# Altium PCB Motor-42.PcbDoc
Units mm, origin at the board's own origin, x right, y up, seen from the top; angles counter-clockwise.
Board outline 41.2 x 41.2 mm, 4 copper layers (Top1, Signal2, Gnd3, Bottom4), stack 0.778 mm thick; 81 components, 66 nets, 267 pads, 151 vias.
Unrouted connection lines stored in the file: 54.
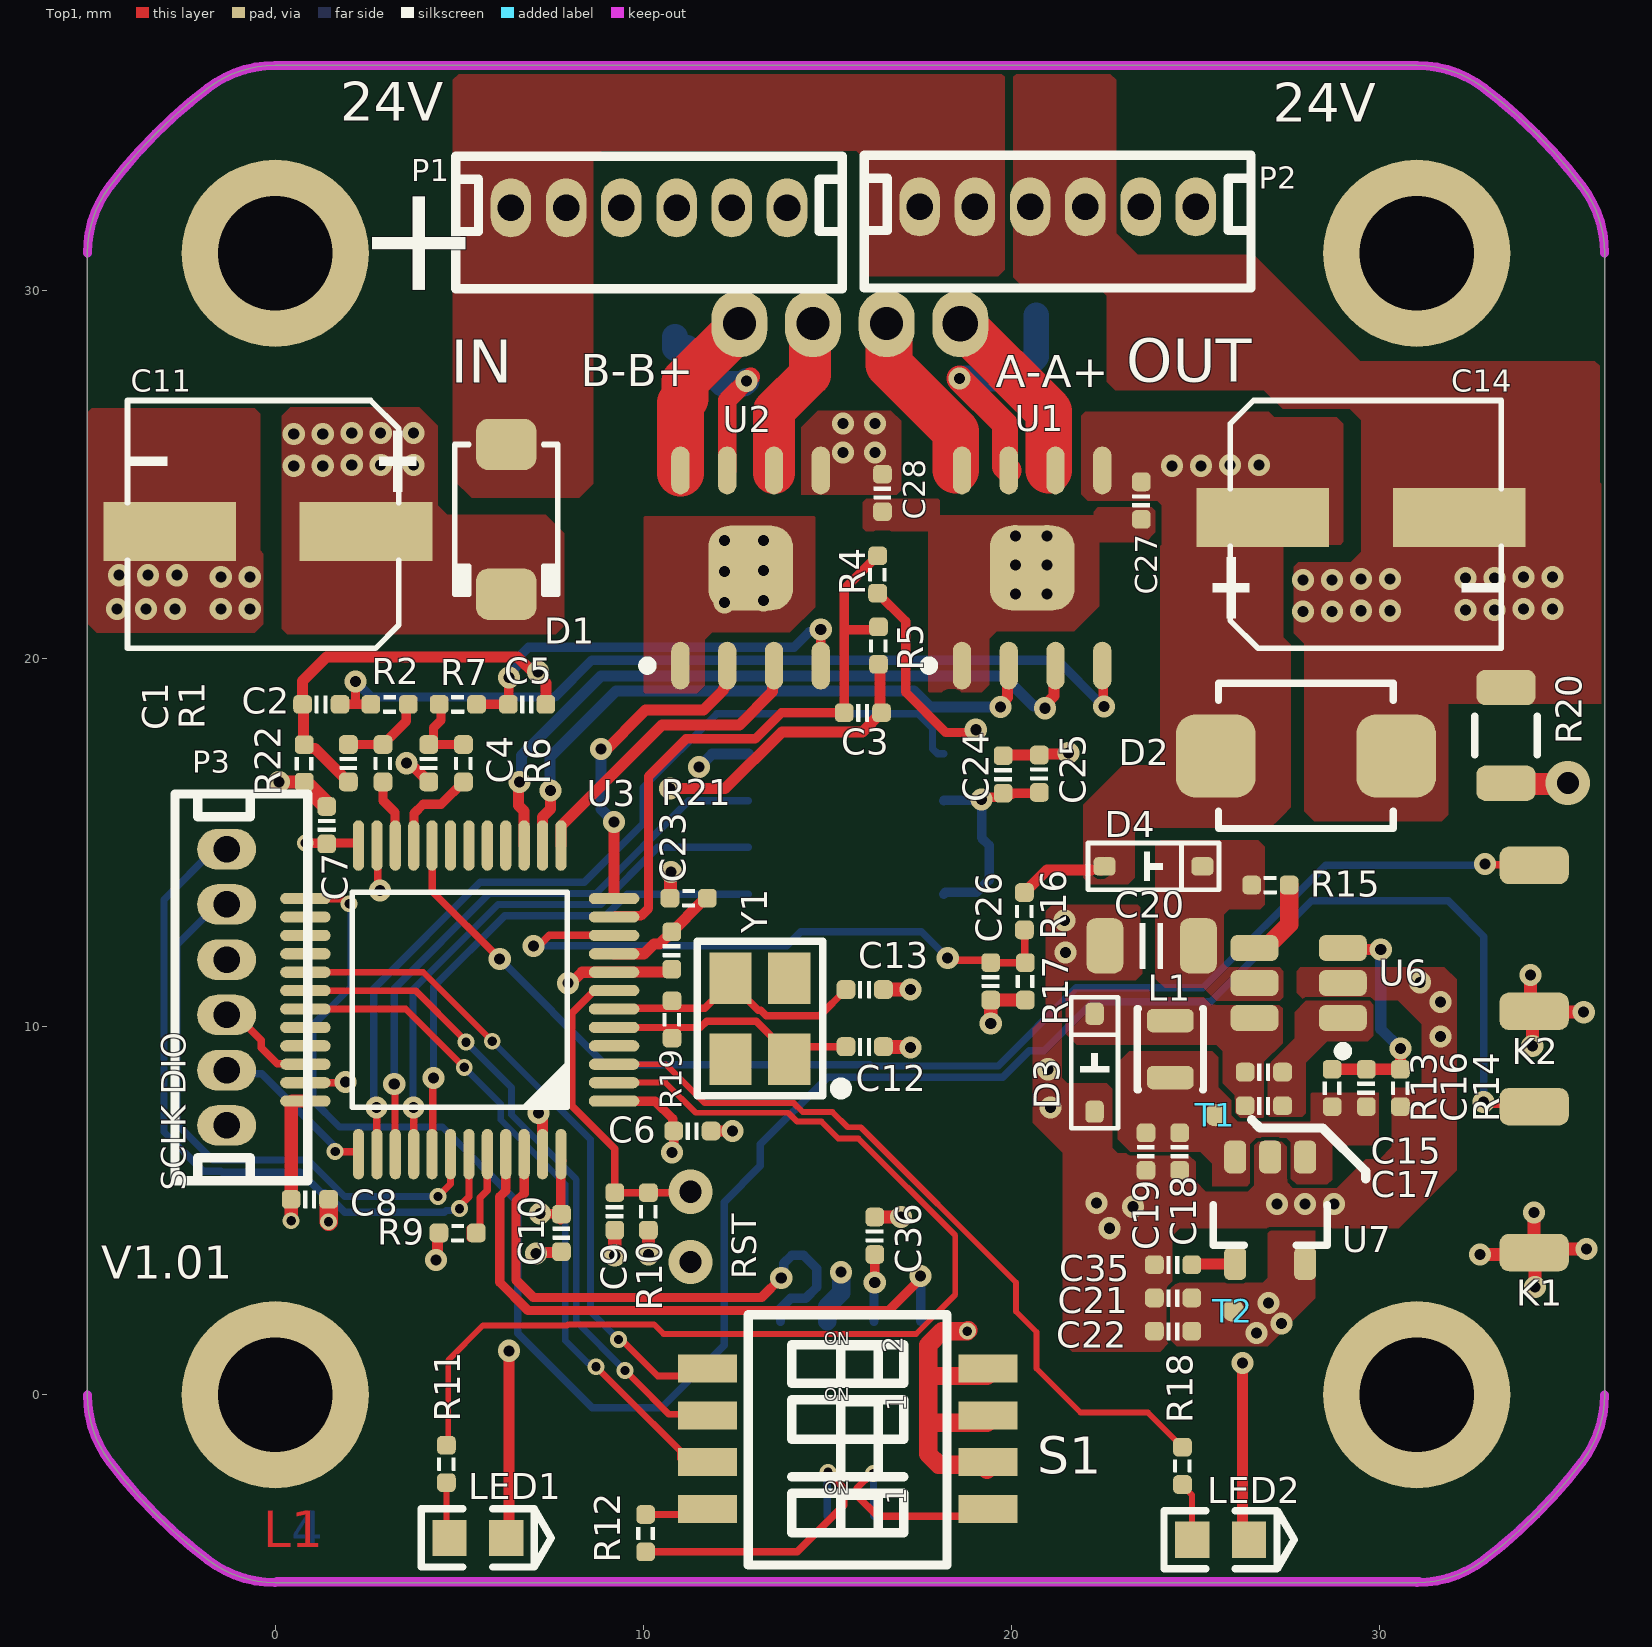
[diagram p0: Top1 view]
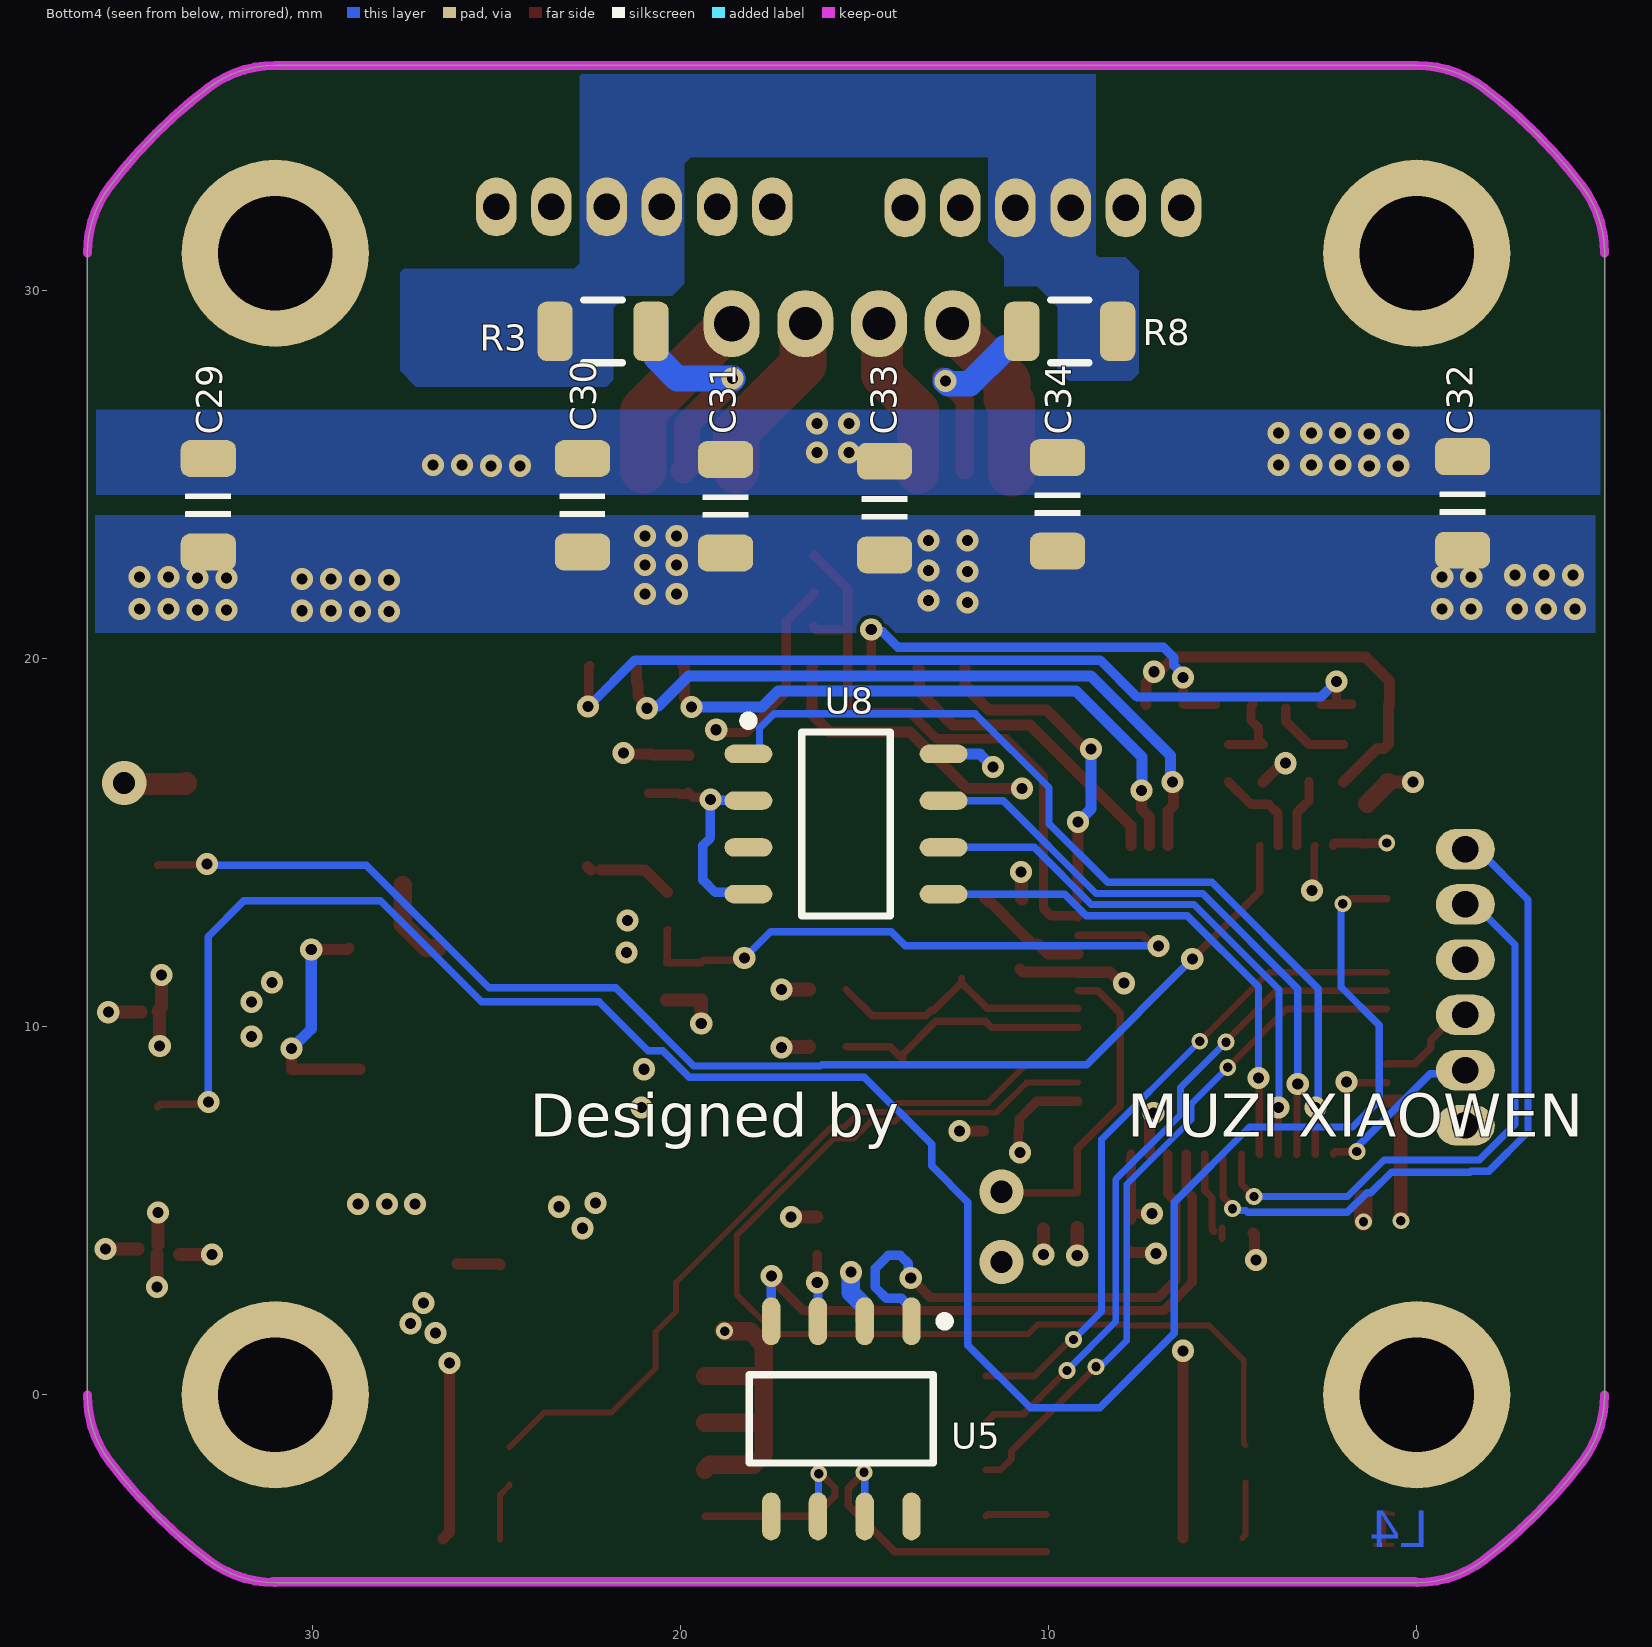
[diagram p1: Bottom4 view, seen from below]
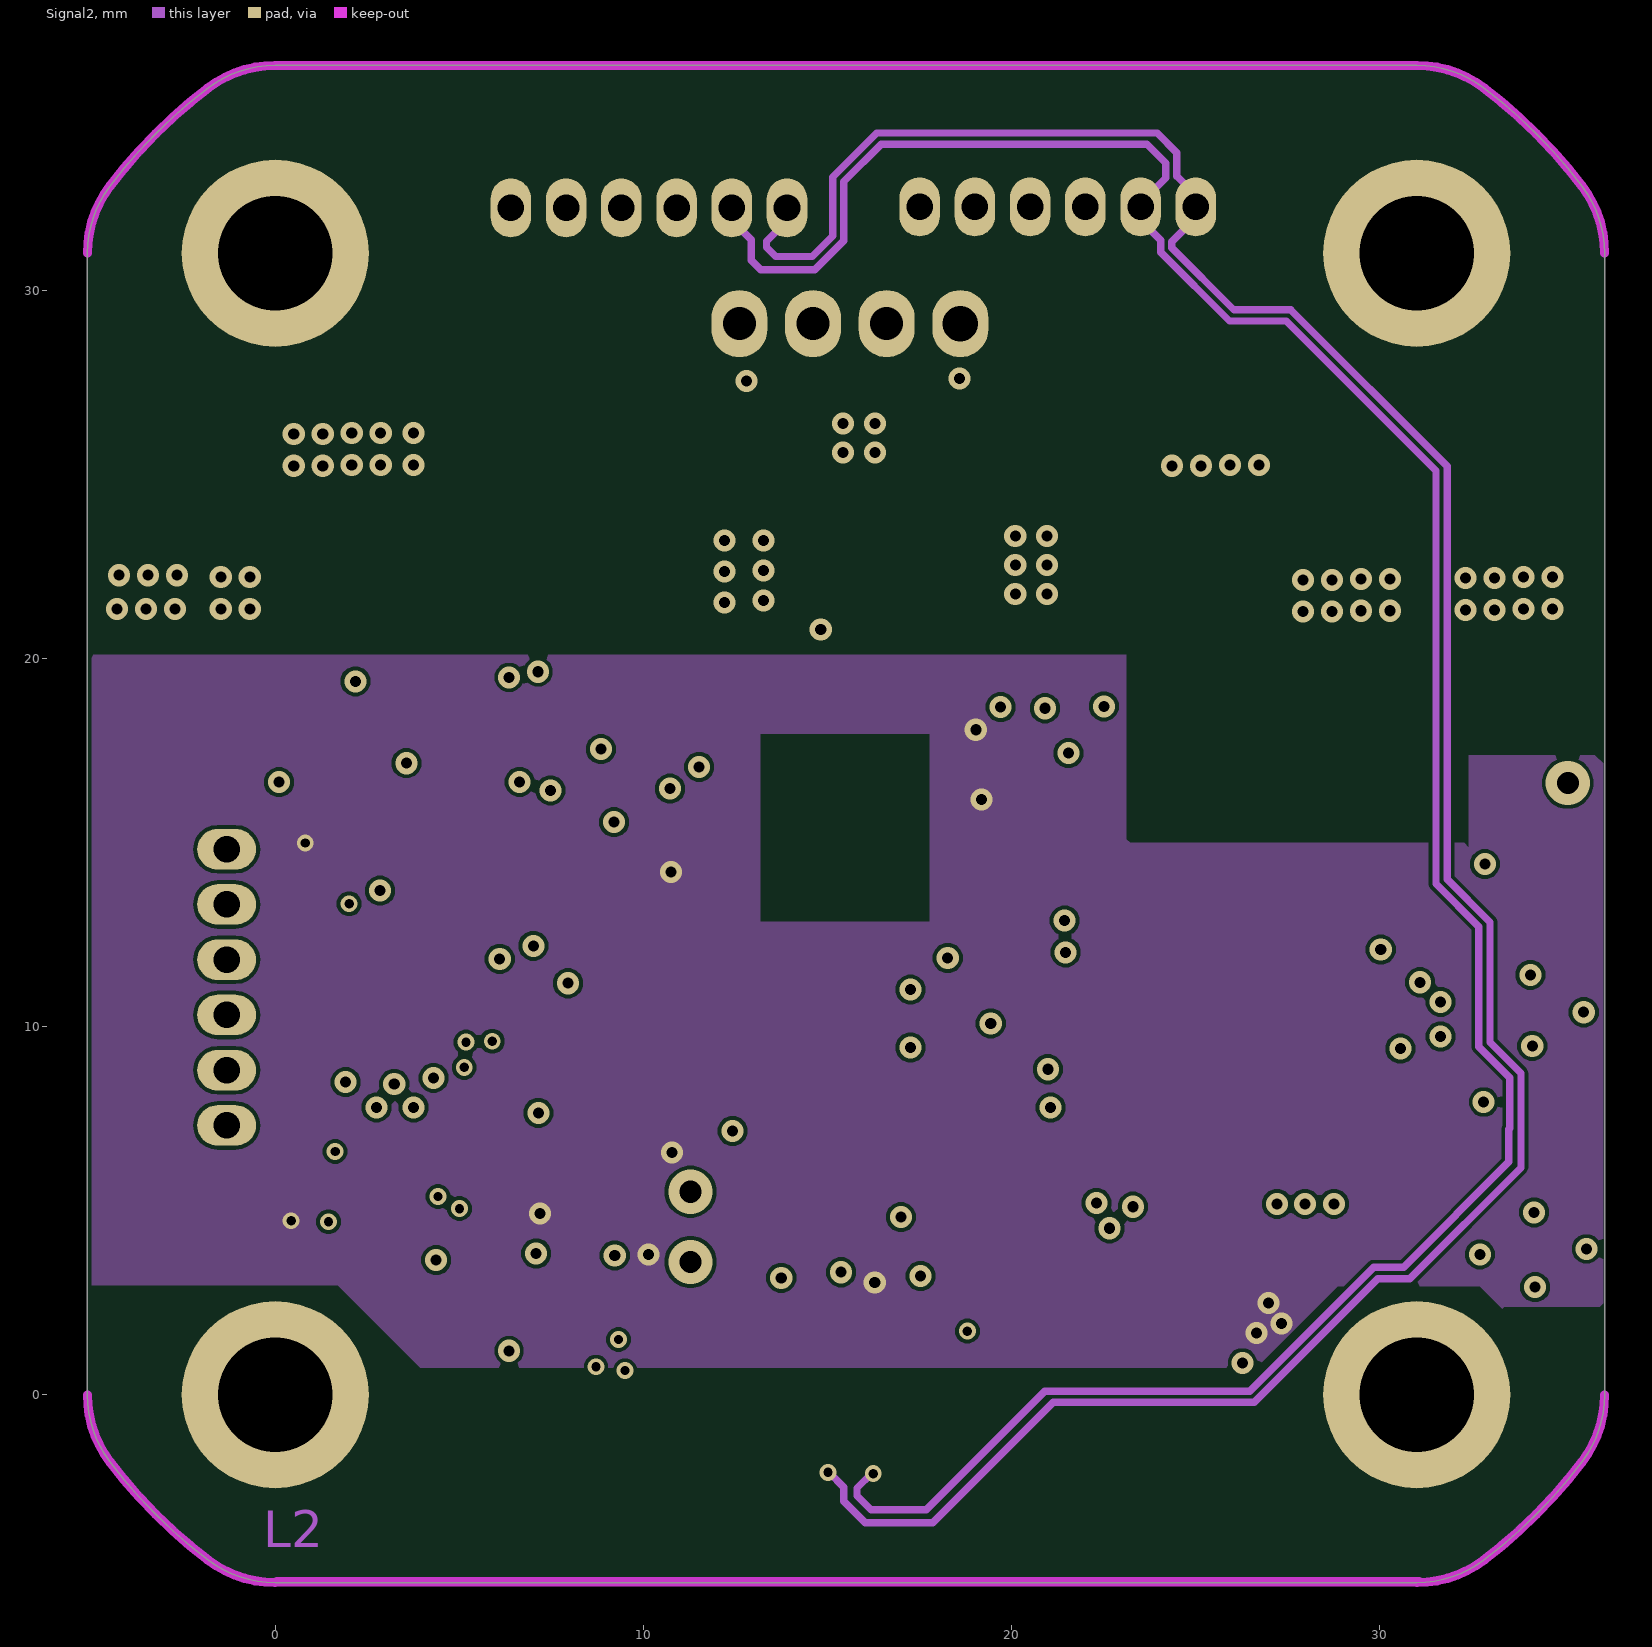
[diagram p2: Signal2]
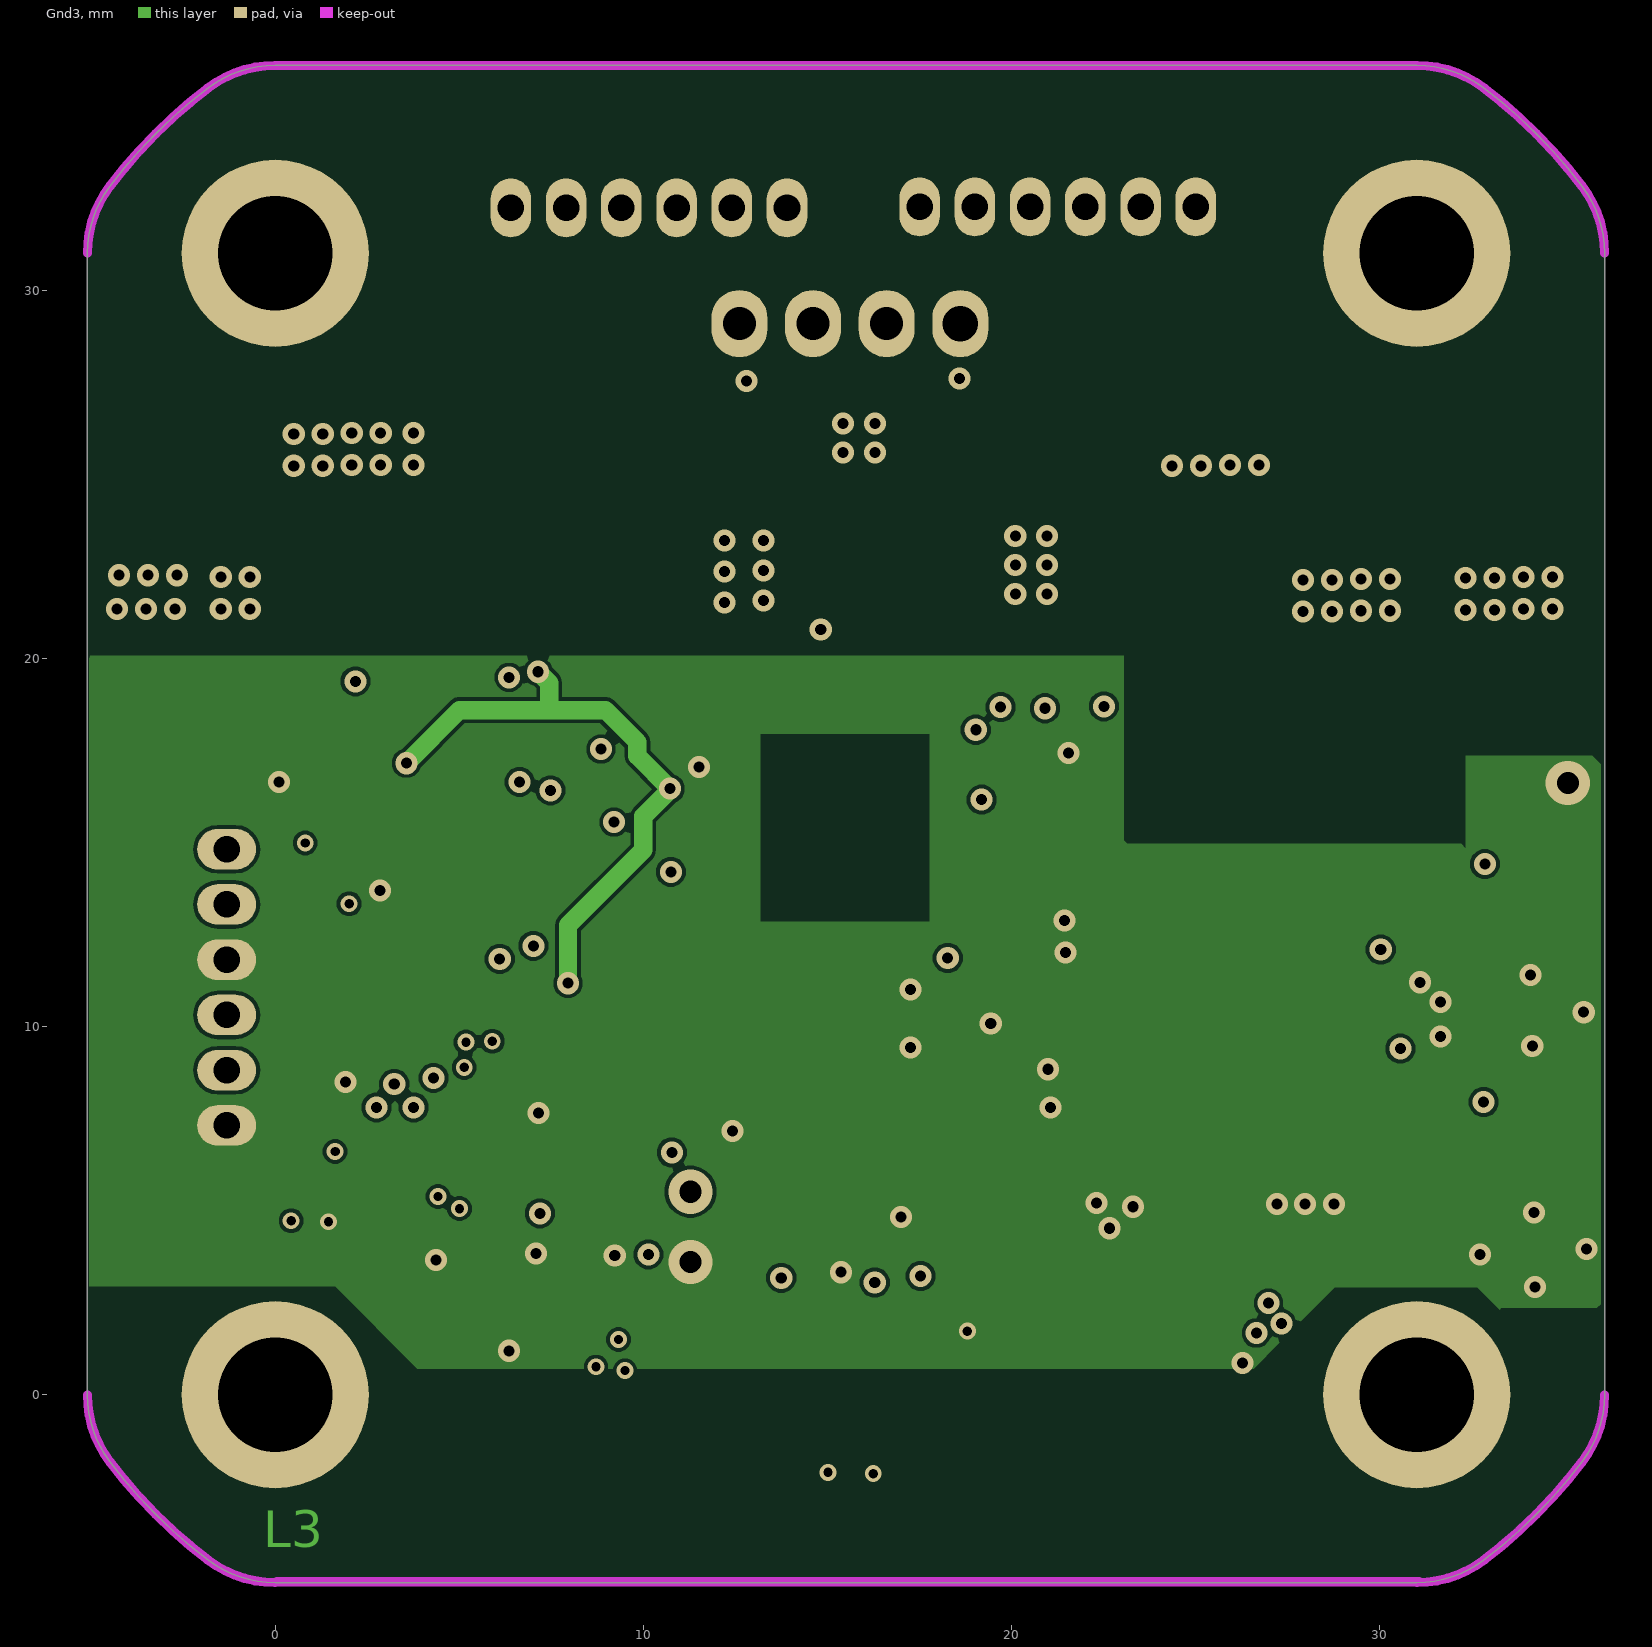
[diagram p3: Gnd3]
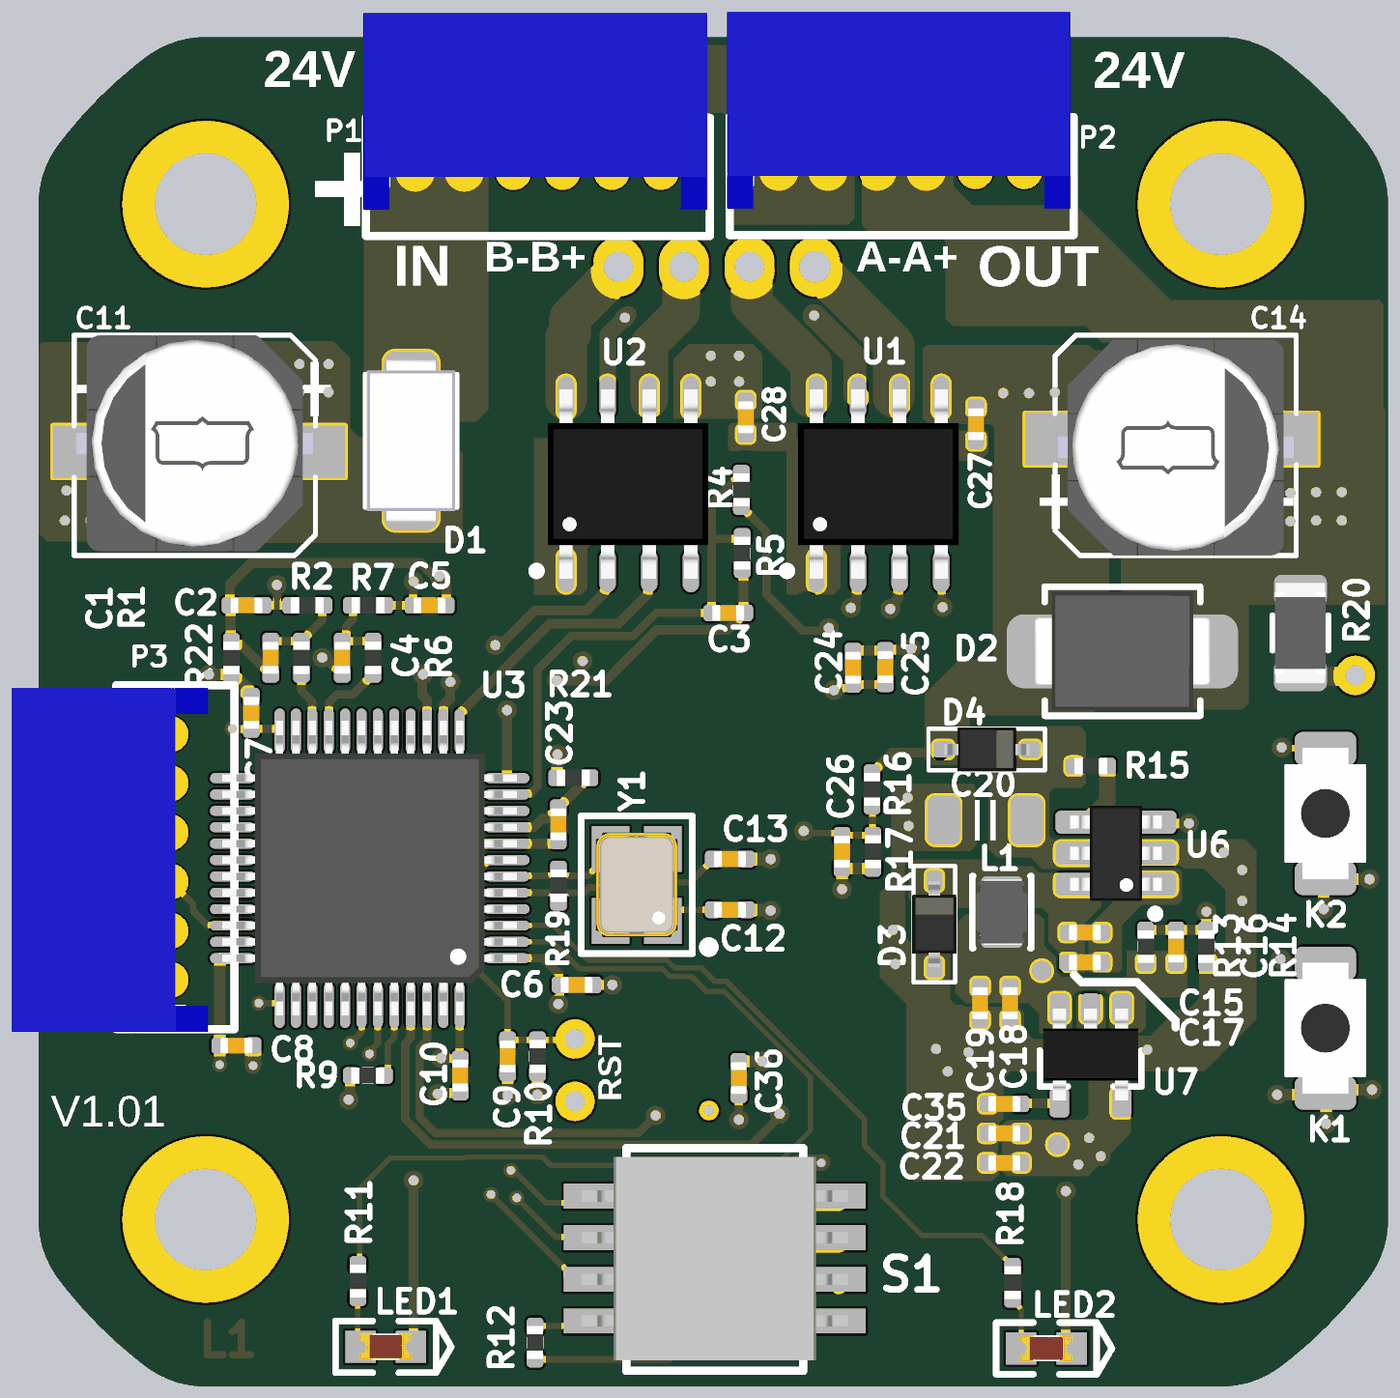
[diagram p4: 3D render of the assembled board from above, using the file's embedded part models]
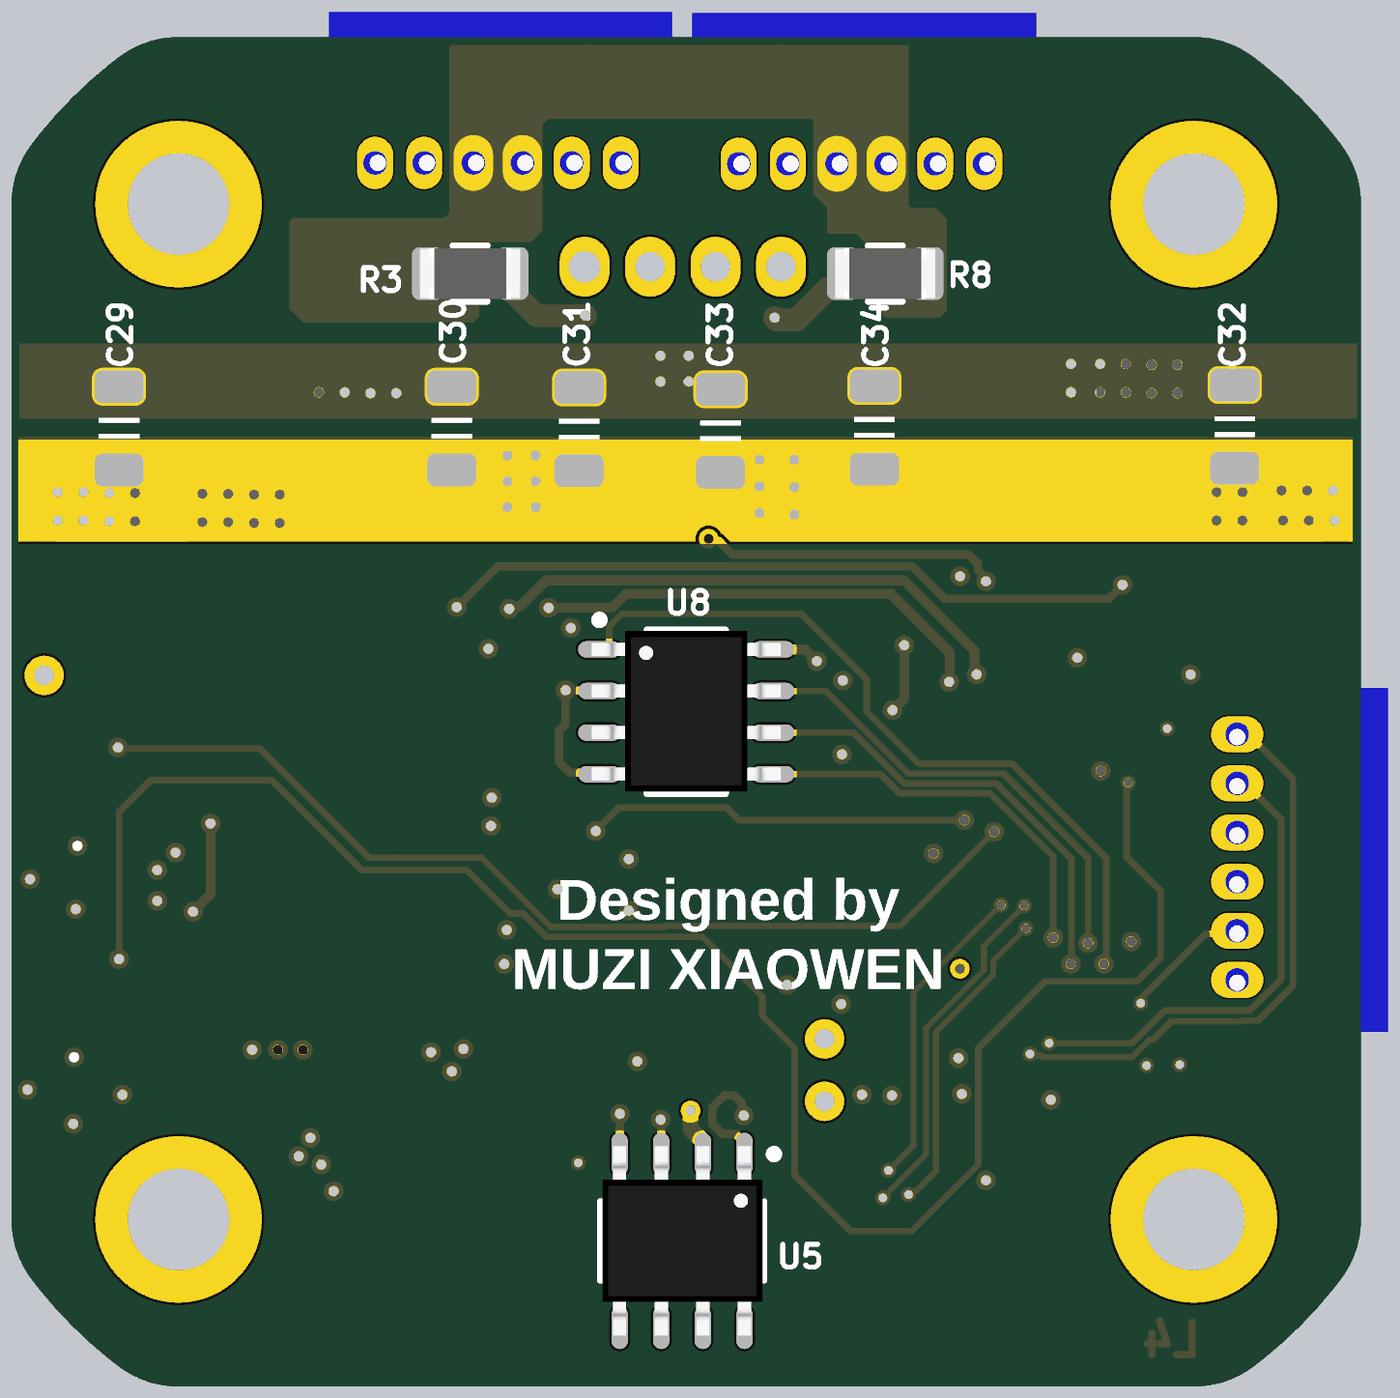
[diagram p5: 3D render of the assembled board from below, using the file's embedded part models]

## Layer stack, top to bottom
Top Solder: solder mask 0.0102, Solder Resist, Dk 3.5
Top1: signal copper 0.0356
Dielectric1: core 0.254, FR-4, Dk 4.2
Signal2: signal copper 0.036
Dielectric2: core 0.254, Dk 4.2
Gnd3: signal copper 0.036
Dielectric3: prepreg 0.127, Dk 4.2
Bottom4: signal copper 0.0356
Bottom Solder: solder mask 0.0102, Solder Resist, Dk 3.5

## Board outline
-4.493,-1.816 cw(c-2.1,-0.006) -5.1,-0.006 -5.1,23 -5.1,31.006 cw(c-2.1,31.006) -4.493,32.816 cw(c6.5,24.5) -1.816,35.493 cw(c-0.006,33.1) -0.006,36.1 31.006,36.1 cw(c31.006,33.1) 32.816,35.493 cw(c24.5,24.5) 35.493,32.816 cw(c33.1,31.006) 36.1,31.006 36.1,-0.006 cw(c33.1,-0.006) 35.493,-1.816 cw(c24.5,6.5) 32.816,-4.493 cw(c31.006,-2.1) 31.006,-5.1 -0.006,-5.1 cw(c-0.006,-2.1) -1.816,-4.493 cw(c6.5,6.5)

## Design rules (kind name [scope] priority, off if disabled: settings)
Clearance [All] p1: gap=0.102 ignorepadtopadclearanceinfootprint=FALSE except(0: Arc-Hole Track-Hole SMDPad-Hole THPad-Hole Via-Hole Fill-Hole Poly-Hole Region-Hole Text-Hole)
ComponentClearance [All] p1: gap=0 collisioncheckmode=3 verticalgap=0 showdistances=FALSE
DiffPairsRouting [All] p1: maxlimit=0.229 minlimit=0.229 mostfreqgap=0.229 toplayer_minwidth=0.381 toplayer_maxwidth=0.381 toplayer_prefwidth=0.381 midlayer1_minwidth=0.381 midlayer1_maxwidth=0.381 midlayer1_prefwidth=0.381 midlayer2_minwidth=0.381 midlayer2_maxwidth=0.381 midlayer2_prefwidth=0.381 bottomlayer_minwidth=0.381 bottomlayer_maxwidth=0.381 bottomlayer_prefwidth=0.381 maxuncoupledlength=12.7
FanoutControl Fanout_BGA [All] p1: bgadir=Out bgaviamode=Centered fanoutstyle=Auto fanoutdirection=Alternating viagrid=0.025 // Fanout_BGA (Default Rule)
HoleSize [All] p1: absolutevalues=TRUE maxlimit=254 minlimit=0.203 maxpercent=80.000 minpercent=20.000
MinimumSolderMaskSliver [All] p1 off: minsoldermaskwidth=0.051
PlaneClearance [All] p1: clearance=0.203
PlaneConnect [All] p1: planeconnectstyle=Direct reliefexpansion=0.508 reliefentries=4 reliefconductorwidth=0.254 reliefairgap=0.254
PolygonConnect [All] p1: connectstyle=Direct reliefconductorwidth=0.254 reliefentries=4 polygonreliefangle="90 Angle" airgapwidth=0.254
RoomDefinition Port [InComponentClass('Port')] p1 off: confinementstyle=ConfineIn formatcopy=TRUE lockcomponents=FALSE outline -13.335,-36.017 37.465,-36.017 37.465,-10.617 -13.335,-10.617
RoomDefinition MCU [InComponentClass('MCU')] p2 off: confinementstyle=ConfineIn formatcopy=TRUE lockcomponents=FALSE outline -13.233,-36.17 37.567,-36.17 37.567,-10.77 -13.233,-10.77
RoomDefinition Interface [InComponentClass('Interface')] p3 off: confinementstyle=ConfineIn formatcopy=TRUE lockcomponents=FALSE outline -14.453,-36.5 36.347,-36.5 36.347,-11.1 -14.453,-11.1
RoomDefinition Drive [InComponentClass('Drive')] p4 off: confinementstyle=ConfineIn formatcopy=TRUE lockcomponents=FALSE outline -13.005,-36.5 37.795,-36.5 37.795,-11.1 -13.005,-11.1
RoomDefinition Power [InComponentClass('Power')] p5 off: confinementstyle=ConfineIn formatcopy=TRUE lockcomponents=FALSE outline -12.675,-36.144 38.125,-36.144 38.125,-10.744 -12.675,-10.744
RoutingVias [All] p1: holewidth=0.203 width=0.406 viastyle="Through Hole" minholewidth=0.152 minwidth=0.305 maxholewidth=0.711 maxwidth=1.27
SilkToSilkClearance [All] p1: silktosilkclearance=0
SilkToSolderMaskClearance [IsPad] p1: minsilkscreentomaskgap=0 clearancetoexposedcopper=TRUE
SolderMaskExpansion [All] p1: expansion=0.076 istentingtop=FALSE
Width GND [(InNet('AGND') OR InNet('GND'))] p1: maxlimit=1.27 minlimit=0.102 preferedwidth=0.254
Width VCC [(InNet('VDD_SYS_3.3V') OR InNet('VDD_AV_3.3V') OR InNet('VDD_5V') OR InNet('VDD1V2-SYS') OR InNet('VDD1V1-EPHY') OR InNet('VDD-CPUX') OR InNet('VDD-CPUS') OR InNet('VDD-CPUFB') OR InNet('VCC-DRAM'))] p2: maxlimit=1.27 minlimit=0.102 preferedwidth=0.254
Width [All] p3: maxlimit=254 minlimit=0.102 preferedwidth=0.102
21 further rules are at their usual default settings.

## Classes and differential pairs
component class Port: C36 K1 K2 P1 P2 P3 R12 S1 U5
component class MCU: C6 C7 C8 C9 C10 C12 C13 C23 LED1 LED2 R9 R10 R11 R18 R19 R21 R22 U3 Y1
component class Interface: C24 C25 C26 R16 R17 U8
component class Drive: C1 C2 C3 C4 C5 C27 C28 R1 R2 R3 R4 R5 R6 R7 R8 R20 U1 U2
component class Power: C11 C14 C15 C16 C17 C18 C19 C20 C21 C22 C29 C30 C31 C32 C33 C34 C35 D1 D2 D3 D4 L1 R13 R14 R15 T1 T2 U6 U7

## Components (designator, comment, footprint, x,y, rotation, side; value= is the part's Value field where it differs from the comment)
C1 "0.1uF" CAP_0402 1.987,17.151 r90 top value=0.1u
C2 "0.1uF" CAP_0402 1.251,18.751 r0 top value=0.1u
C3 "10uF" CAP_0402 15.957,18.523 r180 top value=0.1u
C4 "0.1uF" CAP_0402 4.172,17.151 r90 top value=0.1u
C5 "0.1uF" CAP_0402 6.839,18.751 r180 top value=0.1u
C6 "0.1uF" CAP_0402 11.328,7.163 r180 top value=0.1u
C7 "0.1uF" CAP_0402 1.397,15.469 r270 top value=0.1u
C8 "0.1uF" CAP_0402 0.94,5.309 r180 top value=0.1u
C9 "0.1uF" CAP_0402 9.22,4.978 r90 top value=0.1u
C10 "10uF" CAP_0402 7.772,4.394 r90 top value=0.1u
C11 "220uF/25V" CAP-SMD_BD8.0-L8.3-W8.3-LS9.3-FD -0.076,23.444 r180 top value=150uF/35V
C12 "20pF" CAP_0402 16.008,9.455 r0 top
C13 "20pF" CAP_0402 16.008,11.004 r0 top
C14 "220uF/25V" CAP-SMD_BD8.0-L8.3-W8.3-LS9.3-FD 29.362,23.825 r0 top value=150uF/35V
C15 "0.1uF" CAP_0402 26.848,8.763 r0 top value=0.1u
C16 "100pF" CAP_0402 29.629,8.331 r90 top value=0.1u
C17 "0.1uF" CAP_0402 26.848,7.849 r0 top value=0.1u
C18 "0.1uF" CAP_0402 24.562,6.604 r90 top value=0.1u
C19 "10uF" CAP_0402 23.647,6.604 r90 top value=0.1u
C20 "10uF/50V" 1206-CAP 23.8,12.192 r0 top value=0.1u
C21 "0.1uF" CAP_0402 24.384,2.629 r0 top value=0.1u
C22 "10uF" CAP_0402 24.384,1.727 r0 top value=0.1u
C23 "0.1uF" CAP_0402 10.77,12.065 r90 top value=0.1u
C24 "10uF" CAP_0402 19.767,16.846 r270 top value=0.1u
C25 "0.1uF" CAP_0402 20.752,16.866 r270 top value=0.1u
C26 "0.1uF" CAP_0402 19.431,11.227 r90 top value=0.1u
C27 "0.1uF" CAP_0402 23.52,24.282 r90 top value=0.1u
C28 "0.1uF" CAP_0402 16.491,24.492 r90 top value=0.1u
C29 "10uF/50V" 1206-CAP 32.817,24.155 r270 bottom
C30 "10uF/50V" 1206-CAP 22.657,24.155 r270 bottom
C31 "10uF/50V" 1206-CAP 18.771,24.13 r270 bottom
C32 "10uF/50V" 1206-CAP -1.245,24.206 r270 bottom
C33 "10uF/50V" 1206-CAP 14.453,24.079 r270 bottom
C34 "10uF/50V" 1206-CAP 9.754,24.181 r270 bottom
C35 "0.1uF" CAP_0402 24.384,3.531 r0 top value=0.1u
C36 "0.1uF" CAP_0402 16.281,4.318 r270 top value=0.1u
D1 "SS54" DO-214AC 6.274,23.774 r270 top
D2 "SMBJ28CA" SMBJ-CA_MFG 27.991,17.348 r180 top
D3 "二极管-5819W" SOD-323 22.25,9.017 r90 top
D4 "二极管-5819W" SOD-323 23.851,14.351 r0 top
K1 "TACT 2P" ButtonTACT_3x4x2_180 34.188,5.842 r90 top value=3x4
K2 "TACT 2P" ButtonTACT_3x4x2_180 34.188,12.395 r90 top value=3x4
L1 "6.8uH" IND-201612 24.308,9.384 r270 top
LED1 "LED GREEN" LED-0603 5.512,-3.937 r180 top
LED2 "LED GREEN" LED-0603 25.683,-3.985 r180 top
P1 "Header 6H" CONN-TH_HC-ZH1.5-6A-s 10.148,32.233 r0 top
P2 "Header 6H" CONN-TH_HC-ZH1.5-6A-s 21.249,32.258 r0 top
P3 "Header 6H" CONN-TH_HC-ZH1.5-6A-s -1.321,11.064 r90 top locked
R1 "1K" RES_0402 2.927,17.151 r90 top value=22R
R2 "1K" RES_0402 3.105,18.751 r180 top value=22R
R3 "0.1R" 1206-RES 22.098,28.88 r0 bottom value=22R
R4 "NCP15XH103F03RC" RES_0402 16.358,22.276 r270 top value=10k
R5 "3.3K" RES_0402 16.383,20.345 r90 top value=22R
R6 "1K" RES_0402 5.111,17.151 r90 top value=22R
R7 "1K" RES_0402 4.959,18.751 r0 top value=22R
R8 "0.1R" 1206-RES 9.423,28.88 r180 bottom value=22R
R9 "10K" RES_0402 4.953,4.394 r180 top value=22R
R10 "10K" RES_0402 10.135,4.978 r270 top value=22R
R11 "1K" RES_0402 4.648,-1.88 r270 top value=22R
R12 "120R" RES_0402 10.058,-3.759 r90 top value=22R
R13 "10K" RES_0402 28.702,8.331 r270 top value=22R
R14 "1.8K" RES_0402 30.556,8.331 r90 top value=22R
R15 "1M" RES_0402 27.026,13.843 r0 top value=22R
R16 "10K" RES_0402 20.345,13.132 r270 top value=22R
R17 "1K" RES_0402 20.371,11.227 r270 top value=22R
R18 "1K" RES_0402 24.638,-1.93 r270 top value=22R
R19 "1M" RES_0402 10.776,10.191 r270 top value=22R
R20 "0R" 1206-RES 33.426,17.907 r90 top
R21 "0" RES_0402 11.227,13.487 r180 top value=0R
R22 "0" RES_0402 0.787,17.145 r90 top value=0R
S1 "DSHP04TSGER" SW-SMD_DSHP04TS-S 11.735,-0.559 r90 top
T1 "测试点" TEST_PT 25.527,7.594 r0 top
T2 "测试点" TEST_PT 26.01,2.286 r90 top
U1 "TB67H450FNG" SO-8-PAD 20.555,22.451 r0 top locked
U2 "TB67H450FNG" SO-8-PAD 12.909,22.451 r0 top locked
U3 "STM32F103CBT6" LQFP-48 5.01,10.725 r0 top locked
U5 "SN65HVD232D" so-8 15.627,-0.654 r90 bottom locked
U6 "ME3116" SOT23-6 27.794,11.182 r90 top
U7 "LP2992 3V3" SOT23-5 27.02,4.958 r180 top
U8 "MT6816" SO-8 15.5,15.5 r180 bottom locked
Y1 "XTAL-4" LC-SMD-3225_4P 13.163,10.217 r90 top value="12 MHz"

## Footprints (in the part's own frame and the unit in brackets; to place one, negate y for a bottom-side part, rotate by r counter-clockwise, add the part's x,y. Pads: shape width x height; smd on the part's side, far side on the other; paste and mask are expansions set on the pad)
1206-CAP [mm]
  rrect50% 1x1.5 smd: 1(-1.27,0) 2(1.27,0)
  silkscreen extent -0.3,-0.61 0.3,0.61, body extent -1.5,-0.75 1.5,0.75, height 1.5
1206-RES [mm]
  rrect50% 0.956x1.61 smd paste+0 mask+0: 1(-1.301,0) 2(1.301,0)
  silkscreen extent -0.52,-0.85 0.52,0.85, body extent -1.55,-0.77 1.55,0.77, height 0.65
ButtonTACT_3x4x2_180 [mil]
  rrect50% 40x74 smd: 1(-78,0) 2(78,0)
  body extent -79,-49 79,49, height 63
CAP-SMD_BD8.0-L8.3-W8.3-LS9.3-FD [mm]
  rect 3.6x1.6 smd: 1(-2.54,0) 2(2.794,0)
  silkscreen extent -3.9,-3.56 3.94,3.18, body extent -3.35,-3.55 3.85,3.05, height 7.7
CAP_0402 [mil]
  rrect50% 20x20 smd: 1(-20,0) 2(20,0)
  silkscreen extent -7,-9 7,9, body extent -20,-10 20,10, height 20
CONN-TH_HC-ZH1.5-6A-s [mm]
  oval 1.1x1.6 hole 0.72 paste+0 mask+0.05: 1(-3.75,0) 2(-2.25,0) 3(-0.75,0) 4(0.75,0) 5(2.25,0) 6(3.75,0)
  silkscreen extent -5.25,-2.2 5.25,1.4, body extent -5.34,-1.4 5.16,4.6, height 4
DO-214AC [mil] "SMA"
  rrect50% 55x65 smd: 1(-80,0) 2(80,0)
  silkscreen extent -80,-55 80,55, body extent -98,-53 98,53, height 85
IND-201612 [mm]
  rrect50% 0.635x1.27 smd paste+0 mask+0: 1(-0.774,0) 2(0.774,0)
  silkscreen extent -1.1,-0.9 1.1,0.9, body extent -1,-0.8 1,0.8, height 0.95
LC-SMD-3225_4P [mm]
  rect 1.4x1.15 smd: 1(-1.1,-0.8) 2(1.1,-0.8) 3(1.1,0.8) 4(-1.1,0.8)
  silkscreen extent -2.1,-2.35 2.1,1.7, body extent -1.6,-1.25 1.6,1.25, height 0.61
LED-0603 [mm]
  rect 0.93x0.98 smd: A(0.782,-0.048) C(-0.758,-0.048)
  silkscreen extent -1.99,-0.84 1.55,0.74, body extent -0.79,-0.45 0.81,0.35, height 0.6
LQFP-48 [mil]
  oval 54x12 smd: 1(165,-108.27) 2(165,-88.58) 3(165,-68.9) 4(165,-49.21) 5(165,-29.53) 6(165,-9.84) 7(165,9.84) 8(165,29.53) 9(165,49.21) 10(165,68.9) 11(165,88.58) 12(165,108.27) 25(-165,108.27) 26(-165,88.58) 27(-165,68.9) 28(-165,49.21) 29(-165,29.53) 30(-165,9.84) 31(-165,-9.84) 32(-165,-29.53) 33(-165,-49.21) 34(-165,-68.9) 35(-165,-88.58) 36(-165,-108.27)
  oval 12x54 smd: 13(108.27,165) 14(88.58,165) 15(68.9,165) 16(49.21,165) 17(29.53,165) 18(9.84,165) 19(-9.84,165) 20(-29.53,165) 21(-49.21,165) 22(-68.9,165) 23(-88.58,165) 24(-108.27,165) 37(-108.27,-165) 38(-88.58,-165) 39(-68.9,-165) 40(-49.21,-165) 41(-29.53,-165) 42(-9.84,-165) 43(9.84,-165) 44(29.53,-165) 45(49.21,-165) 46(68.9,-165) 47(88.58,-165) 48(108.27,-165)
  silkscreen extent -115,-115 115,115, body extent -177,-177 177,177, height 61
RES_0402 [mil]
  rrect50% 20x20 smd: 1(-20,0) 2(20,0)
  silkscreen extent -7,-10 7,10, body extent -20,-10 20,10, height 14
SMBJ-CA_MFG [mm]
  rrect50% 2.16x2.26 smd paste+0 mask+0: 1(-2.45,0) 2(2.45,0)
  silkscreen extent -2.37,-1.97 2.37,1.97, body extent -2.7,-1.81 2.7,1.81, height 2.62
so-8 [mm]
  oval 1.3x0.5 smd: 1(2.65,-1.905) 2(2.65,-0.635) 3(2.65,0.635) 4(2.65,1.905) 5(-2.65,1.905) 6(-2.65,0.635) 7(-2.65,-0.635) 8(-2.65,-1.905)
  silkscreen extent -1.2,-2.93 2.77,2.5, body extent -2.89,-2.46 2.89,2.44, height 1.45
SO-8 [mm]
  oval 1.3x0.5 smd: 1(-2.65,1.905) 2(-2.65,0.635) 3(-2.65,-0.635) 4(-2.65,-1.905) 5(2.65,-1.905) 6(2.65,-0.635) 7(2.65,0.635) 8(2.65,1.905)
  silkscreen extent -2.78,-2.5 1.2,2.93, body extent -2.89,-2.44 2.89,2.46, height 1.45
SO-8-PAD [mm]
  oval 0.5x1.3 smd: 1(-1.905,-2.65) 2(-0.635,-2.65) 3(0.635,-2.65) 4(1.905,-2.65) 5(1.905,2.65) 6(0.635,2.65) 7(-0.635,2.65) 8(-1.905,2.65)
  rrect50% 2.3x2.3 smd: 9(0,0)
  silkscreen extent -2.93,-2.77 -2.68,-2.53, body extent -2.46,-2.89 2.44,2.89, height 1.45
SOD-323 [mm]
  rrect50% 0.6x0.5 smd: 1(-1.329,0) 2(1.329,0)
  silkscreen extent -1.78,-0.64 1.78,0.64, body extent -1.3,-0.68 1.3,0.67, height 1.15
SOT23-5 [mm] "SOT23, 3-Leads, Body 3.1x3.0mm (max), Pitch 0.95mm, IPC Medium Density"
  rrect50% 0.6x0.889 smd: 1(-0.95,-1.5) 2(0,-1.5) 3(0.95,-1.5) 4(0.95,1.396) 5(-0.95,1.396)
  silkscreen extent -1.55,-0.2 1.55,0.9, body extent -1.45,-1.48 1.45,1.32, height 1.2
SOT23-6 [mm]
  rrect50% 0.7x1.3 smd: 1(-0.95,-1.2) 2(0,-1.2) 3(0.95,-1.2) 4(0.95,1.2) 5(0,1.2) 6(-0.95,1.2)
  silkscreen extent -1.97,-1.33 -1.73,-1.08, body extent -1.45,-1.4 1.45,1.4, height 1.45
SW-SMD_DSHP04TS-S [mm]
  rect 0.762x1.6 smd: 1(1.27,0) 2(0,0) 3(-1.27,0) 4(-2.54,0) 5(-2.54,-7.62) 6(-1.27,-7.62) 7(0,-7.62) 8(1.27,-7.62)
  silkscreen extent -4.06,-6.51 2.73,-1.11, body extent -3.73,-7.87 2.46,0.25, height 1.71
TEST_PT [mm]
  rrect100% 0.606x0.606 smd: 0(0,0)

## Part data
C1 C2 C3 C4 C5 C6 C7 C8 C9 C10 C12 C13 C15 C16 C17 C18 C19 C20 C21 C22 C23 C24 C25 C26 C27 C28 C35 C36: library part 电容-0402, "Capacitor"
C11 C14 C29 C30 C31 C32 C33 C34: library part CAP, "Capacitor, chip, ceramic"
D1: library part Diode_SMA, "Diode"
D3 D4: "40V"
K1 K2: library part ButtonTACT_3x4x2_180, "Button"
L1: library part 电感-201612
LED1 LED2: library part LED, "LED GRN SGL RA 25mA 4.1V SMD"
P1 P2 P3: "Header, 6-Pin, Right Angle"
R1 R2 R5 R6 R7 R9 R10 R11 R12 R13 R14 R15 R16 R17 R18 R19 R21 R22: library part 电阻-0402, "Resistor"
R3 R8 R20: library part 电阻-1206, "Resistor"
R4: "THERMISTOR 10K OHM NTC 0402 SMD"
S1: library part 218-4LPSTJ, "DIP Switches / SIP Switches 4 pos. low profile Btm Seal Tape J Bend", Manufacturer_Name=CTS, Mouser Part Number=774-218-4LPSTJ
U1 U2: "PWM Chopper Type DC Brushed Motor Driver"
U3: "ARM Cortex-M3 32-bit MCU, 128 KB Flash, 20 KB Internal RAM, 37 I/Os, 48-pin LQFP, -40 to 85 degC, Tray", I/Os (High Current)=37, Operating Frequency(F) (Processor speed) (MHz)=72, Supplier Part Number 1=497-6288-ND, Supply Voltage(Vcc) min (V)=2
U5: Manufacturer="Texas Instruments", Manufacturer Part Number=SN65HVD232DR, Operating Temperature="-40癈 ~ 85癈", Package / Case="8-SOIC (0.154\", 3.90mm Width)", Supplier Device Package=8-SOIC, Supplier Part Number 1=296-26344-2-ND, Voltage - Supply="3 V ~ 3.6 V"
U6: "DC-DC"
U7: library part LP2992, "LDO"
U8: "Magnetic Position Sensor"
Y1: "Crystal"

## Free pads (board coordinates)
  oval 1.524x1.824 hole 0.9: 11(12.604,29.089) 12(14.604,29.089) 13(16.604,29.089)
  oval 1.524x1.824 hole 0.962: 14(18.604,29.089)
  round 5.08 hole 3.1: ""(0,0) ""(0,31) ""(31,0) ""(31,31)

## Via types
v1: diameter 0.6, hole 0.3, Top1 to Bottom4, tented both sides, 130 vias
v2: diameter 0.457, hole 0.254, Top1 to Bottom4, tented both sides, 14 vias
v3: diameter 1.2, hole 0.6, Top1 to Bottom4, 3 vias
v4: diameter 0.457, hole 0.254, Top1 to Bottom4, 2 vias
v5: diameter 0.6, hole 0.3, Top1 to Bottom4, 2 vias

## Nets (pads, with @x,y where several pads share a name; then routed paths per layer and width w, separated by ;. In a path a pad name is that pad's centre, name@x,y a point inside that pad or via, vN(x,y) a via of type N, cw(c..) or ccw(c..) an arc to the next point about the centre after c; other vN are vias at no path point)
ADC_ENC: U3.16
AGND: C1.1 C2.1 C3.1 C4.1 C5.1 C23.1 R5.1 R22.2 U3.8 | length 39.3
  Top1 w0.3: C1.1 1.081,17.549 0.891,17.549 R22.2 0.765,17.675 0.765,18.729 C2.1 0.743,19.386 1.397,20.041 6.579,20.041 v1@7.061,19.558 ; v1(3.562,17.151) 3.619,17.094 3.721,17.094 C4.1 ; v1(7.137,19.634) 7.195,19.577 7.195,19.475 7.347,19.323 C5.1 ; v1(7.95,11.176) 8.031,11.176 8.329,11.474 9.2,11.474 U3.8 U3.8 10.688,11.476 C23.1 ; v1(10.72,16.459) 12.219,16.459 13.76,18 15.943,18 C3.1 16.424,18.564 16.424,19.796 R5.1
  Gnd3 w0.5: v1(3.562,17.151) 5.004,18.593 7.442,18.593 ; v1(7.137,19.634) 7.442,19.329 7.442,18.593 ; v1(7.95,11.176) 7.95,12.751 9.994,14.794 9.994,15.706 10.72,16.432 v1(10.72,16.459) 9.834,17.346 9.834,17.725 8.966,18.593 7.442,18.593
BUTTON_1: K1.2 U3.25 | length 59
  Top1 w0.2: U3.25 1.797,13.475 1.937,13.335 v2(2.007,13.335) ; v1(32.817,7.95) 32.88,7.887 34.125,7.887 K1.2
  Bottom4 w0.2: v2@2.057,13.335 2.057,11.074 1.016,10.033 1.016,8.001 1.747,7.27 4.541,7.27 6.585,5.226 6.585,1.668 8.609,-0.356 10.49,-0.356 12.192,1.346 12.192,5.231 13.175,6.214 13.175,6.799 15.002,8.626 19.759,8.626 20.473,9.341 20.879,9.341 22.206,10.668 25.4,10.668 28.143,13.411 31.852,13.411 32.817,12.446 v1(32.817,7.95)
BUTTON_2: K2.2 U3.20 | length 35.4
  Top1 w0.2: U3.20 4.268,14.907 4.268,13.664 v1(6.096,11.836) ; v1(32.851,14.411) 32.869,14.394 34.171,14.394 K2.2
  Bottom4 w0.2: v1(6.096,11.836) 8.966,8.966 16.153,8.966 16.192,8.928 19.634,8.928 21.755,11.049 25.197,11.049 28.524,14.376 32.817,14.376 v1(32.851,14.411)
CAN_H: P1.6 P2.6 R12.1 U5.7 | length 79.7
  Top1 w0.2: R12.1 14.173,-4.267 15.443,-2.997 15.443,-2.54 v4(15.011,-2.108)
  Signal2 w0.2: P1.6 13.898,31.881 13.342,31.325 13.342,31.159 13.589,30.912 14.585,30.912 15.142,31.469 15.142,33.073 16.334,34.265 23.952,34.265 24.486,33.731 24.486,33.096 24.999,32.583 P2.6 24.999,31.962 24.351,31.314 24.351,31.148 26.038,29.461 27.582,29.461 31.827,25.217 31.827,13.995 32.99,12.832 32.99,9.575 33.83,8.736 33.83,6.169 30.81,3.15 29.939,3.15 26.587,-0.203 21.133,-0.203 17.856,-3.48 16.027,-3.48 15.443,-2.896 15.443,-2.515 15.037,-2.108 v4(15.011,-2.108)
  Bottom4 w0.2: U5.7@14.989,-3.301 U5.7 14.992,-2.204 v4@15.011,-2.184
CAN_L: P1.5 P2.5 S1.5 U5.6 | length 76.4
  Top1 w0.2: v4(16.238,-2.141) 16.191,-2.141 15.799,-2.533 15.799,-2.743 16.358,-3.302 S1.5@19.329,-3.302
  Signal2 w0.2: P1.5 12.398,31.9 12.929,31.369 12.929,30.81 13.183,30.556 14.656,30.556 15.443,31.344 15.443,32.948 16.455,33.96 23.673,33.96 24.181,33.452 24.181,33.045 23.499,32.364 23.499,31.906 24.049,31.356 24.049,31.023 25.913,29.159 27.457,29.159 31.521,25.095 31.521,13.874 32.688,12.707 32.688,9.45 33.528,8.611 33.528,7.239 33.503,7.214 33.503,6.325 30.645,3.467 29.83,3.467 26.462,0.098 20.901,0.098 17.678,-3.124 16.18,-3.124 15.799,-2.743 15.799,-2.533 16.191,-2.141 v4(16.238,-2.141)
  Bottom4 w0.2: v4@16.231,-2.134 16.246,-2.149 16.246,-3.289 U5.6
CAN_RX: U3.45 U5.4 | length 17
  Top1 w0.254: U3.45 6.26,5.538 6.096,5.375 6.096,3.053 6.863,2.286 16.662,2.286 17.526,3.15 v1(17.526,3.226)
  Bottom4 w0.254: v1(17.526,3.226) 17.529,3.223 17.529,1.999 U5.4
CAN_TX: U3.46 U5.1 | length 14.8
  Top1 w0.254: U3.46 6.76,5.467 6.538,5.246 6.538,3.114 7.01,2.642 13.208,2.642 v1(13.741,3.175)
  Bottom4 w0.254: U5.1 13.722,2.344 13.994,2.616 14.402,2.616 14.707,2.921 14.707,3.429 14.351,3.785 14.024,3.785 13.805,3.566 13.805,3.239 v1(13.741,3.175)
GND: C6.1 C7.1 C8.1 C9.1 C10.1 C12.2 C13.2 C18.1 C19.1 C20.1 C21.1 C22.1 C24.1 C25.1 C26.1 C35.1 C36.1 D3.1 K1.1 K2.1 LED1.C LED2.C P3.1 P3.4 R9.2 R14.1 R17.2 R20.1 R22.1 S1.6 S1.7 S1.8 U3.23 U3.35 U3.47 U5.2 U6.2 U7.2 U8.8 | length 43.9
  Top1 w0.2: U3.35 v1@1.82,8.475 ; U3.23 2.78,14.896 2.78,13.756 v1(2.845,13.691)
  Top1 w0.3: v1(4.369,3.658) 4.407,3.696 4.407,4.356 R9.2 ; LED1.C@6.346,-3.889 6.35,-3.885 v1(6.35,1.194) ; v1(7.087,3.835) 7.112,3.861 7.747,3.861 C10.1 ; v5(7.145,7.653) 7.145,7.572 7.259,7.459 7.259,6.535 U3.47 ; C6.1@11.76,7.163 v1@12.243,7.163 ; C24.1 19.786,17.373 C25.1 20.777,17.399 21.514,17.399 v1(21.539,17.424) ; v1(26.264,0.864) 26.264,-3.734 LED2.C@26.441,-3.912
  Top1 w0.354: v1(0.102,16.637) R22.1 ; v1(9.22,3.785) C9.1@9.22,4.547 ; C36.1 v1@16.891,4.826 ; v1(19.431,10.084) C26.1 R17.2 ; v1(32.715,3.81) K1.1@33.604,3.81 ; v1(34.087,11.405) 34.087,10.516 K2.1 ; v1(34.138,9.474) K2.1@34.138,10.363 ; K1.1@34.188,4.064 v1(34.188,4.953) ; v1(34.214,2.921) K1.1@34.214,3.81 ; K2.1@34.646,10.389 v1(35.535,10.389) ; K1.1@34.722,3.962 v1(35.611,3.962)
  Top1 w0.39: C12.2 16.529,9.442 17.24,9.442 v1(17.253,9.429) ; C13.2 v1(17.253,11.004)
  Top1 w0.5: R22.1 0.787,16.612 C7.1@1.346,16.053 ; v2(1.448,4.699) C8.1 ; v2@18.821,1.753 v2(18.796,1.727) 18.11,1.727 17.729,1.346 17.729,0.473 ; S1.6@19.329,-2.032 19.198,-1.901 18.022,-1.901 17.729,-1.608 17.729,-0.66 ; S1.7@19.329,-0.762 17.831,-0.762 17.729,-0.66 ; S1.8@19.329,0.508 17.764,0.508 17.729,0.473 ; 17.729,-0.66 17.729,0.473
  Top1 w0.6: R20.1 33.446,16.586 v3@35.027,16.586
  Bottom4 w0.3: v1(11.512,17.049) 11.868,17.405 U8.8
  Bottom4 w0.5: U5.2 14.992,2.396 15.367,2.771 v5(15.367,3.327)
  other v1: 22.657,4.521 16.993,4.826 23.292,5.105 27.203,5.182 27.965,5.182 28.753,5.182 22.301,5.207 12.421,7.163 21.057,7.798 1.911,8.49 20.98,8.839 31.648,9.728 31.648,10.668 31.09,11.201 21.463,12.014 21.438,12.878
  other v3: 11.278,3.607 35.103,16.612
ID0: S1.1 U3.29 | length 18.2
  Top1 w0.18: U3.29 4.019,11.475 v2(5.893,9.601) ; v2(9.322,1.499) 9.397,1.499 10.387,0.508 S1.1@11.709,0.508
  Bottom4 w0.18: v2(5.893,9.601) 8.56,6.934 8.56,2.261 v2(9.322,1.499)
ID1: S1.2 U3.30 | length 18.3
  Top1 w0.18: U3.30 3.808,10.975 v2@5.08,9.703 ; v2(9.5,0.66) 9.754,0.406 10.693,-0.533 11.481,-0.533 S1.2@11.709,-0.762
  Bottom4 w0.18: v2(5.182,9.576) 6.415,8.343 6.415,7.606 8.179,5.842 8.179,1.981 v2(9.5,0.66)
ID2: S1.3 U3.31 | length 18.9
  Top1 w0.18: U3.31 3.546,10.475 v2(5.131,8.89) ; v2(8.712,0.762) 9.474,0 11.006,-1.532 11.006,-1.741 11.297,-2.032 S1.3@11.709,-2.032
  Bottom4 w0.18: v2(5.131,8.89) 6.123,7.898 6.123,7.466 7.874,5.715 7.874,1.473 8.203,1.144 8.476,0.871 8.528,0.871 8.637,0.762 v2(8.712,0.762)
IN_AM: U1.2 U3.14 | length 16.9
  Top1 w0.3: U3.14 U3.14 7.261,15.694 7.474,15.906 v1(7.474,16.414) ; v1(19.7,18.675) 19.7,18.756 19.881,18.938 19.881,19.763 U1.2
  Bottom4 w0.3: v1(7.474,16.414) 7.459,16.429 7.459,17.314 9.252,19.107 17.343,19.107 17.775,18.675 v1(19.7,18.675)
IN_AP: U1.3 U3.15 | length 19.3
  Top1 w0.3: v1(6.635,16.643) 6.61,16.618 6.61,16.008 6.759,15.859 U3.15@6.759,14.917 ; v1(20.904,18.644) 20.904,18.725 21.151,18.972 21.151,19.309 21.19,19.347 U1.3 ; U3.15@6.759,14.917 U3.15
  Bottom4 w0.3: v1(6.635,16.643) 6.693,16.7 6.693,17.361 8.845,19.513 19.781,19.513 20.593,18.701 20.847,18.701 v1(20.904,18.644)
IN_BM: U2.2 U3.12 | length 8.8
  Top1 w0.3: v1@8.896,17.43 10.06,18.594 11.634,18.594 12.174,19.134 12.174,19.179 12.274,19.279 U2.2@12.274,19.733 ; U3.12 v1(9.201,15.551)
  Bottom4 w0.3: v1(8.845,17.532) 8.845,15.906 v1(9.201,15.551)
IN_BP: U2.3 U3.13 | length 8.4
  Top1 w0.3: U3.13 7.76,15.449 10.503,18.192 12.604,18.192 13.506,19.094 13.506,19.695 U2.3@13.544,19.733
IN_PWM_A: R1.1 U3.22 | length 1.9
  Top1 w0.254: R1.1 2.927,16.135 3.25,15.812 3.25,14.926 U3.22
IN_PWM_B: R6.1 U3.21 | length 2.6
  Top1 w0.254: U3.21 3.77,14.926 3.77,15.784 4.019,16.033 4.502,16.033 R6.1
MT6816_AUX_CS: U3.17
MT6816_CS: U3.38 U8.1 | length 24.5
  Top1 w0.2: v1(2.749,7.804) 2.755,7.798 2.755,6.539 U3.38
  Bottom4 w0.2: v1(2.749,7.804) 2.673,7.88 2.673,11.03 5.559,13.916 8.394,13.916 9.988,15.51 9.988,16.491 11.995,18.497 17.456,18.497 17.85,18.103 17.85,17.544 17.989,17.405 U8.1
NetC1_2: C1.2 R1.2 R2.1 | length 2.2
  Top1 w0.254: C1.2 R1.2 3.562,18.294 R2.1@3.562,18.65
NetC4_2: C4.2 R6.2 R7.1 | length 2.2
  Top1 w0.254: R7.1 4.502,18.7 4.502,18.319 4.299,18.116 4.299,17.786 C4.2 R6.2
NetC9_2: C9.2 R10.1 U3.7 | length 8.5
  Top1 w0.2: U3.7 8.667,10.975 8.052,10.36 8.052,7.848 9.22,6.68 C9.2 R10.1 10.973,5.486 v3@10.998,5.512
  other v3: 11.278,5.512
NetC12_1: C12.1 R19.2 U3.5 Y1.1 | length 7
  Top1 w0.2: U3.5 11.55,9.975 11.715,10.141 13.064,10.141 13.963,9.242 Y1.1 14.026,9.179 14.301,9.455 C12.1
NetC13_1: C13.1 R19.1 U3.6 Y1.3 | length 7.4
  Top1 w0.2: U3.6 9.219,10.493 11.407,10.493 11.411,10.496 11.668,10.496 Y1.3@12.363,11.192 ; Y1.3 Y1.3@12.363,11.192 ; C13.1 14.789,10.293 13.339,10.293 13.189,10.442 13.113,10.442 Y1.3@12.363,11.192
NetC15_1: C15.1 C17.1 D3.2 L1.1 U6.6
NetC15_2: C15.2 C17.2 U6.1
NetC16_2: C16.2 R13.1 R14.2 U6.3 | length 6.4
  Top1 w0.3: R13.1 C16.2 R14.2 v1(30.556,9.398) ; U6.3 29.035,12.09 v1(30.023,12.09)
  Bottom4 w0.3: v1(30.023,12.09) 30.023,9.931 v1(30.556,9.398)
NetC20_2: C20.2 D4.2 R15.1 U6.5
NetC23_2: C23.2 R21.1 U3.9 | length 3.2
  Top1 w0.3: U3.9 U3.9 10.02,11.976 10.287,12.243 10.439,12.243 C23.2 11.58,13.383 11.631,13.383 R21.1
NetC35_2: C35.2 U7.4 | length 1.2
  Top1 w0.3: C35.2 24.908,3.546 26.054,3.546 U7.4
NetLED1_A: LED1.A R11.2 | length 1.5
  Top1 w0.16: R11.2 4.648,-3.807 LED1.A
NetLED2_A: LED2.A R18.2 | length 1.6
  Top1 w0.16: R18.2 24.638,-2.464 24.901,-2.727 LED2.A
NetR3_1: R3.1 U1.7 | length 6.5
  Top1 w0.7: v1(18.58,27.597) 19.82,26.357 19.82,25.201 U1.7
  Bottom4 w0.7: v1(18.58,27.597) 20.078,27.597 20.669,28.187 R3.1@20.669,29.311
NetR8_1: R8.1 U2.7 | length 5.5
  Top1 w0.5: U2.7 12.274,27.006 v1@12.909,27.641
  Bottom4 w0.7: R8.1@10.853,28.733 10.853,28.425 11.179,28.425 12.146,27.458 12.726,27.458 v1(12.802,27.534)
NetR9_1: R9.1 U3.44 | length 2.5
  Top1 w0.2: R9.1@5.289,4.248 R9.1@5.289,4.519 ; R9.1@5.512,4.445 5.561,4.495 5.561,5.35 5.76,5.548 U3.44
NetR12_2: R12.2 S1.4 | length 1.7
  Top1 w0.18: R12.2 11.659,-3.251 S1.4@11.709,-3.302
NetR15_2: R15.2 U6.4 | length 2.3
  Top1 w0.5: U6.4 26.894,12.132 27.534,12.772 R15.2
OUT_A+: pad.14 U1.6 | length 5
  Top1 w1.27: pad.14 18.624,29.089 21.006,26.707 U1.6@21.006,25.116
OUT_A-: pad.13 U1.8 | length 4.8
  Top1 w1.27: pad.13 16.668,29.026 16.668,27.972 18.483,26.157 U1.8@18.483,25.116
OUT_B+: pad.12 U2.6 | length 4.5
  Top1 w1.143: U2.6@13.544,25.033 13.544,26.727 14.517,27.7 14.517,29.002 pad.12
OUT_B-: pad.11 U2.8 | length 4.7
  Top1 w1.27: U2.8@11.004,25.033 11.004,26.93 11.131,27.057 11.131,27.527 12.604,29 pad.11
PC13: R11.1 U3.2 | length 29.6
  Top1 w0.16: R11.1 4.699,-1.321 4.699,0.94 5.639,1.88 7.925,1.88 7.954,1.909 10.289,1.909 10.547,1.651 17.399,1.651 18.466,2.718 18.466,4.329 15.835,6.96 15.291,6.96 14.834,7.417 14.173,7.417 13.932,7.658 11.417,7.658 10.601,8.475 U3.2
PC14: R18.1 U3.3 | length 20.8
  Top1 w0.16: U3.3 10.609,8.975 11.664,7.92 14.084,7.92 14.326,7.678 15.131,7.678 15.545,7.264 15.9,7.264 20.117,3.048 20.117,2.261 20.676,1.702 20.676,0.711 21.869,-0.483 23.698,-0.483 R18.1
PC15: U3.4
PGND: C11.2 C14.2 C27.1 C28.1 C29.2 C30.2 C31.2 C32.2 C33.2 C34.2 D2.1 P1.3 P1.4 P2.3 P2.4 R3.2 R8.2 R20.2 U1.1 U1.9 U2.1 U2.9
  other v1: 27.909,21.266 28.696,21.266 29.483,21.291 30.271,21.291 32.328,21.317 33.116,21.317 -4.299,21.342 -3.511,21.342 -2.724,21.342 -1.479,21.342 -0.692,21.342 33.903,21.342 34.69,21.342 12.198,21.52 13.265,21.571 20.097,21.748 20.961,21.748 27.909,22.129 28.696,22.129 29.483,22.155 30.271,22.155 32.328,22.18 33.116,22.18 -1.479,22.206 -0.692,22.206 33.903,22.206 34.69,22.206 -4.248,22.256 -3.46,22.256 -2.673,22.256 12.198,22.358 13.265,22.383 20.097,22.536 20.961,22.536 12.198,23.196 13.265,23.196 20.097,23.323 20.961,23.323
POWER_U: C26.2 R16.2 R17.1 U3.10 | length 16.9
  Top1 w0.2: v1@7.163,12.192 7.446,12.475 U3.10 ; v1(18.263,11.862) 18.326,11.798 19.367,11.798 C26.2 R17.1 20.358,11.748 20.358,12.611 R16.2
  Bottom4 w0.2: v1(7.01,12.192) 13.894,12.192 14.275,12.573 17.551,12.573 v1(18.263,11.862)
SPI1_MISO: U3.40 U8.6 | length 15.2
  Top1 w0.2: U3.40@3.759,6.535 v1@3.759,7.803
  Bottom4 w0.2: v1(3.758,7.804) 3.74,7.822 3.74,11.004 6.048,13.312 8.837,13.312 10.389,14.865 U8.6
SPI1_MOSI: U3.41 U8.5 | length 14.2
  Top1 w0.2: U3.41 4.279,6.553 4.279,8.585 v1(4.299,8.604)
  Bottom4 w0.2: v1(4.299,8.604) 4.299,11.08 6.229,13.011 8.978,13.011 9.562,13.595 U8.5
SPI1_SCK: U3.39 U8.7 | length 16.2
  Top1 w0.2: v1(3.232,8.439) 3.251,8.42 3.251,6.543 U3.39
  Bottom4 w0.2: v1(3.232,8.439) 3.232,11.03 5.816,13.614 8.712,13.614 11.233,16.135 U8.7
SPI2_MISO: U3.27
SPI2_MOSI: U3.28
SPI2_SCK: U3.26
SWCLK: P3.2 U3.37 | length 4.9
  Top1 w0.2: P3.2 P3.2@-1.071,8.814 ; v2(1.626,6.604) 2.211,6.604 2.26,6.556 U3.37
  Bottom4 w0.2: P3.2 -1.227,8.72 -0.363,8.72 1.576,6.78 1.576,6.653 v2(1.626,6.604)
SWDIO: P3.3 U3.34 | length 2.8
  Top1 w0.2: P3.3 -1.071,10.314 -0.385,9.628 -0.385,9.427 0.057,8.986 0.808,8.986 U3.34
TEMP: C3.2 R4.1 R5.2 U3.11 | length 16.3
  Top1 w0.254: U3.11 9.23,13.004 9.931,13.004 10.135,13.208 10.135,16.789 11.157,17.811 13.036,17.811 13.747,18.523 C3.2 15.449,20.777 ; R4.1@16.345,22.796 R4.1 15.449,21.875 15.449,20.777 ; R5.2@16.37,20.866 R5.2 16.307,20.777 15.449,20.777
UART1_RX: P3.6 U3.43 | length 19.1
  Top1 w0.2: v2(5.004,5.055) 5.004,5.124 5.26,5.38 U3.43
  Bottom4 w0.2: P3.6 -1.655,14.814 -3.023,13.446 -3.023,7.137 -1.959,6.074 -1.473,6.074 -1.445,6.045 0.686,6.045 1.245,5.486 1.351,5.486 1.883,4.955 4.598,4.955 4.648,5.005 4.955,5.005 v2(5.004,5.055)
UART1_TX: P3.5 U3.42 | length 15.9
  Top1 w0.2: v2(4.42,5.385) 4.76,5.725 U3.42
  Bottom4 w0.2: P3.5 -1.571,13.314 -2.667,12.218 -2.667,7.347 -1.695,6.375 0.889,6.375 1.88,5.385 v2(4.42,5.385)
USB_DM: U3.32
USB_DP: U3.33
VCC: C11.1 C14.1 C27.2 C28.2 C29.1 C30.1 C31.1 C32.1 C33.1 C34.1 D1.2 D2.2 D4.1 R16.1 U1.5 U2.5 | length 2.2
  Top1 w0.3: R16.1 20.957,14.251 22.165,14.251 ; D4.1@22.421,14.251 D4.1
  other v1: 0.502,25.228 1.289,25.228 24.353,25.228 25.14,25.228 2.077,25.254 2.864,25.254 3.753,25.254 25.927,25.254 26.715,25.254 15.424,25.584 16.287,25.584 0.502,26.092 1.289,26.092 2.077,26.117 2.864,26.117 3.753,26.117 15.424,26.371 16.287,26.371
VCC_3V3: C6.2 C7.2 C8.2 C10.2 C21.2 C22.2 C24.2 C25.2 C36.2 R4.2 R10.2 R21.2 T2.0 U3.1 U3.24 U3.36 U3.48 U5.3 U7.5 U8.2 U8.4 | length 25.5
  Top1 w0.254: U3.36@0.809,7.985 U3.36 ; v2(0.813,14.986) 0.825,14.973 1.384,14.973 C7.2 1.499,14.961 1.524,14.986 2.236,14.986 2.26,14.963 U3.24 ; v1(7.188,4.928) 7.201,4.915 7.76,4.915 7.823,4.851 C10.2 ; C10.2@7.747,4.75 7.753,4.756 7.753,4.902 U3.48@7.753,6.379 ; U3.48 7.76,6.379 U3.48@7.783,6.356 ; U3.1 10.313,7.975 10.795,7.493 C6.2@10.795,7.163 ; v1(10.77,6.579) 10.82,6.629 C6.2 ; v1(16.281,3.048) C36.2 ; R4.2 17.12,21.006 17.12,19.075 18.212,17.983 v1@18.974,17.983 ; v1(19.183,16.16) 19.249,16.227 19.656,16.227 C24.2 C24.2@19.789,16.36 ; C24.2@19.789,16.309 20.018,16.309 20.041,16.332 C25.2@20.853,16.332
  Top1 w0.354: v1(10.135,3.81) R10.2 R10.2@10.135,4.496 ; R21.2@10.719,13.462 10.731,13.475 10.731,14.186 v1(10.744,14.199)
  Top1 w0.36: v2(0.432,4.724) C8.2 0.432,7.947 0.459,7.975 U3.36
  Bottom4 w0.254: U5.3 16.262,3.029 v1(16.281,3.048) ; U8.4 18.197,13.642 19.052,13.642 19.386,13.976 19.386,14.92 19.183,15.123 v1(19.183,16.16) 19.17,16.148 18.163,16.148 U8.2
  other v1: 26.645,1.676 27.33,1.93 26.975,2.489 19.025,18.059
VCC_5V: C16.1 C18.2 C19.2 L1.2 R13.2 T1.0 U7.1 U7.3
VCC_IN: D1.1 P1.1 P1.2 P2.1 P2.2
VREF_A: C2.2 R2.2 U1.4 | length 23.9
  Top1 w0.254: C2.2 2.178,18.751 ; v1(2.178,19.373) 2.178,18.751 ; R2.2 2.178,18.751 ; U1.4 22.482,19.779 22.482,18.717 v1(22.504,18.694)
  Bottom4 w0.254: v1(2.178,19.373) 2.603,18.948 7.595,18.948 8.591,19.945 21.24,19.945 v1@22.434,18.751
VREF_B: C5.2 R7.2 U2.4 | length 11.7
  Top1 w0.254: R7.2 C5.2 6.34,18.761 6.34,19.472 v1(6.35,19.482) ; U2.4@14.814,19.733 U2.4 v1@14.814,20.682
  Bottom4 w0.254: v1(6.35,19.482) 6.35,19.575 6.596,19.821 6.596,20.019 6.877,20.301 14.087,20.301 14.503,20.717 14.748,20.717 v1(14.814,20.783)
pads on no net: U3.18 U3.19 U5.5 U5.8 U8.3 Y1.2 Y1.4

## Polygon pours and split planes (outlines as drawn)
PGND on Top1 "NONET_L01_P-001" (solid, pour order 95): 20.041,35.789 20.041,30.353 20.396,29.997 22.428,29.997 22.581,29.845 22.581,27.508 22.809,27.28 26.848,27.28 27.356,26.772 29.185,26.772 29.489,26.467 29.489,22.657 29.642,22.504 35.23,22.504 35.966,23.241 35.966,27.94 35.839,28.067 29.464,28.067 26.568,30.963 23.419,30.963 22.835,31.547 22.835,35.712 22.68,35.867 20.119,35.867
VCC_IN on Top1 "VCC_IN_L01_P092" (solid, pour order 92): 4.826,24.841 4.826,35.712 5.105,35.992 19.609,35.992 19.812,35.789 19.812,30.556 19.634,30.378 16.104,30.378 15.9,30.582 15.9,33.655 15.773,33.782 8.865,33.782 8.636,33.553 8.636,24.74 8.255,24.359 5.334,24.359 4.851,24.841
VCC on Top1 "VCC_L01_P091" (solid, pour order 91): 0.178,20.803 0.33,20.65 7.62,20.65 7.849,20.879 7.849,23.393 7.341,23.901 4.674,23.901 4.42,24.155 4.42,26.314 3.912,26.822 0.406,26.822 0.178,26.594
PGND on Top1 "PGND_L01_P089" (solid, pour order 89): -0.406,22.936 -0.406,26.645 -0.559,26.797 -4.978,26.797 -5.08,26.695 -5.08,20.926 -4.851,20.698 -0.562,20.698 -0.33,20.93 -0.33,22.962 -0.381,23.012
VCC on Top1 "VCC_L01_P087" (solid, pour order 87): 21.895,24.451 21.895,26.594 21.996,26.695 26.975,26.695 27.127,26.543 28.829,26.543 29.007,26.365 29.007,23.165 28.931,23.089 24.079,23.089 24.079,24.155 23.952,24.282 22.064,24.282
VCC on Top1 "VCC_L01_P069" (solid, pour order 69): 23.343,14.046 23.343,15.265 23.47,15.392 27.026,15.392 27.584,15.951 26.797,15.951 25.654,17.094 23.012,17.094 21.946,16.027 21.946,14.046 22.123,13.868 23.165,13.868
PGND on Top1 "PGND_L01_P078" (solid, pour order 78): 22.225,23.851 22.225,23.978 22.403,24.155 23.749,24.155 23.901,24.003 23.901,23.419 23.638,23.155 22.032,23.155 22.032,23.53 22.123,23.622
GND on Top1 "GND_L01_P077" (solid, pour order 77): 23.546,11.43 23.368,11.252 21.539,11.252 21.361,11.074 21.361,8.611 21.514,8.458 22.581,8.458 22.733,8.306 22.733,6.706 22.885,6.553 24.765,6.553 24.994,6.325 24.994,5.791 25.273,5.512 26.416,5.512 26.594,5.69 26.594,6.814 26.765,6.985 27.229,6.985 27.483,6.731 27.483,5.766 27.635,5.613 28.829,5.613 29.616,6.401 29.997,6.401 30.328,6.731 30.328,8.255 30.404,8.331 31.013,8.331 31.14,8.458 31.14,10.058 30.48,10.719 27.94,10.719 27.737,10.922 27.737,11.506 27.838,11.608 31.75,11.608 32.08,11.278 32.08,6.096 30.505,4.521 24.562,4.521 24.359,4.318 24.359,1.499 24.028,1.168 21.641,1.168 21.387,1.422 21.387,6.579 20.574,7.391 20.574,9.957 20.93,10.312 20.93,13.132 21.107,13.31 23.419,13.31 23.495,13.233 23.495,11.963 23.546,11.913
VCC_3V3 on Top1 "VCC_3V3_L01_P076" (solid, pour order 76): 24.486,3.048 26.822,3.048 26.949,3.175 26.949,4.387 27.02,4.458 28.245,4.458 28.245,2.616 26.949,1.321 24.486,1.321 24.308,1.499 24.308,2.87
NetC15_2 on Top1 "NETC15_2_L01_P074" (solid, pour order 74): 26.924,8.763 26.924,8.915 27.686,9.677 27.686,10.389 27.991,10.693 29.718,10.693 29.82,10.592 29.82,9.754 29.667,9.601 28.575,9.601 27.991,9.017 27.991,7.645 27.889,7.544 27,7.544 26.924,7.62 26.924,8.903 27.013,8.992
NetC15_1 on Top1 "NETC15_1_L01_P073" (solid, pour order 73): 26.06,8.128 25.73,8.458 25.73,9.322 25.552,9.5 21.768,9.5 21.463,9.804 21.463,10.795 21.666,10.998 23.724,10.998 23.927,10.795 25.222,10.795 25.425,10.592 27.254,10.592 27.356,10.49 27.356,9.55 26.848,9.042 26.848,7.544 26.772,7.468 26.264,7.468 26.06,7.671
VCC_5V on Top1 "VCC_5V_L01_P072" (solid, pour order 72): 28.118,7.442 28.118,8.179 28.143,8.204 29.972,8.204 29.972,6.934 29.82,6.782 28.219,6.782 28.067,6.934 28.067,7.391
VCC_5V on Top1 "VCC_5V_L01_P071" (solid, pour order 71): 22.885,9.017 22.885,6.934 23.216,6.604 25.121,6.604 25.451,6.274 25.451,5.664 26.391,5.664 26.467,5.74 26.467,6.807 26.645,6.985 27.457,6.985 27.584,6.858 27.584,5.867 27.737,5.715 28.575,5.715 28.702,5.842 28.702,7.112 28.397,7.417 26.137,7.417 25.959,7.595 25.959,8.001 25.603,8.357 25.603,9.169 25.451,9.322 23.19,9.322
NetC20_2 on Top1 "NETC20_2_L01_P070" (solid, pour order 70): 26.695,15.062 26.873,14.884 26.873,13.31 26.746,13.183 25.908,13.183 25.756,13.03 25.756,11.709 25.857,11.608 27.28,11.608 27.381,11.506 27.381,10.795 27.28,10.693 25.552,10.693 25.197,11.049 24.155,11.049 23.901,11.303 23.901,14.91 24.054,15.062
PGND on Top1 "PGND_L01_P068" (solid, pour order 68): 27.788,22.606 29.21,22.606 30.531,23.927 30.531,24.409 30.937,24.816 35.941,24.816 36.017,24.74 36.017,18.771 31.852,18.771 31.852,15.748 31.674,15.57 28.219,15.57 27.94,15.85 27.94,20.396 27.661,20.676 27.661,22.606 27.673,22.619
VCC on Top1 "VCC_L01_P063" (solid, pour order 63): 24.028,23.063 24.028,15.621 24.13,15.519 27.153,15.519 27.584,15.951 27.584,20.371 27.381,20.574 27.381,23.048 27.203,23.226 27.066,23.089 24.079,23.089
PGND on Top1 "PGND_L01_P059" (solid, pour order 59): 18.002,24.326 18.04,24.288 18.04,23.552 17.938,23.45 16.033,23.45 15.957,23.526 15.957,24.238 16.059,24.339 16.071,24.326
PGND on Top1 "PGND_L01_P055" (solid, pour order 55): 17.761,19.081 17.735,19.107 17.735,23.857 17.761,23.882 22.358,23.882 22.383,23.857 22.383,21.418 21.698,20.732 19.589,20.732 19.386,20.529 19.386,19.285 19.183,19.081 18.472,19.081
PGND on Top1 "PGND_L01_P054" (solid, pour order 54): 10.039,19.056 10.014,19.081 10.014,23.831 10.039,23.857 14.636,23.857 14.662,23.831 14.662,21.393 13.976,20.707 11.868,20.707 11.665,20.504 11.665,19.259 11.461,19.056 10.75,19.056
VCC on Top1 "VCC_L01_P044" (solid, pour order 44): 14.281,24.441 14.281,26.27 14.738,26.727 16.719,26.727 16.999,26.447 16.999,24.568 16.872,24.441 15.817,24.441
PGND on Bottom4 "NONET_L01_P-001" (solid, pour order 94): 7.747,27.534 7.544,27.736 7.544,30.531 7.899,30.886 8.636,30.886 8.712,30.963 8.712,35.865 8.865,36.017 22.53,36.017 22.733,35.814 22.733,30.734 22.885,30.582 27.508,30.582 27.61,30.48 27.61,27.813 27.178,27.381 21.996,27.381 21.819,27.559 21.819,29.515 21.488,29.845 20.218,29.845 19.888,30.175 19.888,33.426 19.71,33.604 11.671,33.604 11.633,33.566 11.633,31.318 11.201,30.886 11.201,30.099 10.312,30.099 9.754,29.54 9.754,27.838 9.449,27.534
PGND on Bottom4 "PGND_L04_P039" (solid, pour order 39): -4.851,20.698 -4.851,23.882 35.89,23.882 35.89,20.698
VCC on Bottom4 "VCC_L04_P040" (solid, pour order 40): -4.978,24.441 -4.978,26.752 35.865,26.752 35.865,24.441
PGND on Bottom Solder "PGND_L04_P066" (solid, pour order 66): -4.851,20.629 -4.851,23.813 35.891,23.813 35.891,20.629
GND on Gnd3 "GND_L03_P090" (solid, pour order 90): -5.131,20.066 23.038,20.066 23.038,15.062 23.139,14.961 32.207,14.961 32.334,14.834 32.334,17.348 35.763,17.348 35.992,17.12 35.992,2.464 35.89,2.362 33.299,2.362 33.249,2.311 32.639,2.921 28.778,2.921 26.568,0.711 3.861,0.711 1.626,2.946 -5.055,2.946 -5.055,19.99
VCC_3V3 on Signal2 "VCC_3V3_L02_P080" (solid, pour order 80): -5.055,20.091 23.114,20.091 23.114,15.088 23.216,14.986 32.283,14.986 32.41,14.859 32.41,17.374 35.839,17.374 36.068,17.145 36.068,2.489 35.966,2.388 33.376,2.388 33.325,2.337 32.715,2.946 28.854,2.946 26.645,0.737 3.937,0.737 1.702,2.972 -4.978,2.972 -4.978,20.015

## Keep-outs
Keep-Out Layer:
  lines w0.254: -5.1,-0.006 ccw(c-2.1,-0.006) -4.493,-1.816 ccw(c6.5,6.5) -1.816,-4.493 ccw(c-0.006,-2.1) -0.006,-5.1 ; -5.1,31.006 cw(c-2.1,31.006) -4.493,32.816 cw(c6.5,24.5) -1.816,35.493 cw(c-0.006,33.1) -0.006,36.1 31.006,36.1 cw(c31.006,33.1) 32.816,35.493 cw(c24.5,24.5) 35.493,32.816 cw(c33.1,31.006) 36.1,31.006 ; 0.048,-5.075 31.06,-5.075 ; 31.006,-5.1 ccw(c31.006,-2.1) 32.816,-4.493 ccw(c24.5,6.5) 35.493,-1.816 ccw(c33.1,-0.006) 36.1,-0.006

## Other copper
Top1:
  pour cut-out: 13.487,17.628 13.487,13 17.475,13 17.475,17.628
  text "L1" at -0.329,-4.139 h0.99
Signal2:
  pour cut-out: 13.189,17.938 13.189,12.858 17.761,12.858 17.761,17.938
  text "L2" at -0.329,-4.139 h0.99
Gnd3:
  pour cut-out: 13.189,17.938 13.189,12.858 17.761,12.858 17.761,17.938
  text "L3" at -0.329,-4.139 h0.99
Bottom4:
  pour cut-out: 13.189,17.938 13.189,12.858 17.761,12.858 17.761,17.938
  text "L4" at -0.329,-4.139 h0.99

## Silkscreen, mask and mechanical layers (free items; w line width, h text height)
Top Overlay:
  lines w0.254: 26.518,7.468 26.742,7.244 28.443,7.244 29.616,6.071 29.616,5.867
  text "24V" at 1.761,34.244 h1.8
  text "24V" at 27.085,34.218 h1.8
  text "+" at 1.651,32.969 h5.08 r270
  text "OUT" at 23.114,27.127 h2
  text "B-B+" at 8.299,27.102 h1.5
  text "IN" at 4.767,27.097 h2
  text "A-A+" at 19.563,27.076 h1.5
  text "SCLK DIO" at -2.216,5.537 h1.14 r90
  text "RST" at 13.283,3.141 h1.14 r90
  text "V1.01" at -4.724,2.845 h1.52
Bottom Overlay:
  text "Designed by            MUZI XIAOWEN" at 24.087,6.63 h2
Mechanical 1:
  lines w0.254: -5.046,0.019 ccw(c-2.046,0.019) -4.439,-1.791 ccw(c6.554,6.525) -1.762,-4.468 ccw(c0.048,-2.075) 0.048,-5.075 31.06,-5.075 ccw(c31.06,-2.075) 32.869,-4.468 ccw(c24.554,6.525) 35.546,-1.791 ccw(c33.154,0.019) 36.154,0.019 36.154,31.031 ccw(c33.154,31.031) 35.546,32.84 ccw(c24.554,24.525) 32.869,35.517 ccw(c31.06,33.125) 31.06,36.125 0.048,36.125 ccw(c0.048,33.125) -1.762,35.517 ccw(c6.554,24.525) -4.439,32.84 ccw(c-2.046,31.031) -5.046,31.031 -5.046,0.019
Mechanical 13:
  lines w0.254: -5.046,31.031 ccw(c-5.046,31.031) -5.046,31.031 ; 36.154,0.019 ccw(c36.154,0.019) 36.154,0.019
